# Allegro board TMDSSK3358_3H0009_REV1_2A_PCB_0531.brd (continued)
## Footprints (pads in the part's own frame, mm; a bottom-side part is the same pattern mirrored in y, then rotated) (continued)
CN52271-0679
  rect 0.6x1.9 smd: 1(-2.5,4.225) 2(-1.5,4.225) 3(-0.5,4.225) 4(0.5,4.225) 5(1.5,4.225) 6(2.5,4.225)
  rect 2.1x2.8 smd: 7(-5.65,1.875) 8(5.65,1.875)
CNFPC1X40-0P5MM
  rect 0.25x1.2 smd: 1(-9.75,3.575) 2(-9.25,3.575) 3(-8.75,3.575) 4(-8.25,3.575) 5(-7.75,3.575) 6(-7.25,3.575) 7(-6.75,3.575) 8(-6.25,3.575) 9(-5.75,3.575) 10(-5.25,3.575) 11(-4.75,3.575) 12(-4.25,3.575) 13(-3.75,3.575) 14(-3.25,3.575) 15(-2.75,3.575) 16(-2.25,3.575) 17(-1.75,3.575) 18(-1.25,3.575) 19(-0.75,3.575) 20(-0.25,3.575) 21(0.25,3.575) 22(0.75,3.575) 23(1.25,3.575) 24(1.75,3.575) 25(2.25,3.575) 26(2.75,3.575) 27(3.25,3.575) 28(3.75,3.575) 29(4.25,3.575) 30(4.75,3.575) 31(5.25,3.575) 32(5.75,3.575) 33(6.25,3.575) 34(6.75,3.575) 35(7.25,3.575) 36(7.75,3.575) 37(8.25,3.575) 38(8.75,3.575) 39(9.25,3.575) 40(9.75,3.575)
  custom 0.6x0.6 smd: 41(-11.85,0.875) 42(11.85,0.875)
CNMM8130-CUS-TI
  rect 0.58x0.5 smd: 1(-1.05,0) 4(1.05,0)
  rect 0.8x0.75 smd: 2(-0.95,-1.025) 3(0.95,-1.025) 5(0.95,1.025) 6(-0.95,1.025)
DLW5BTN501SQ2
  custom 0.425x0.425 smd: 1(-1.6,-1.5) 2(1.6,-1.5) 3(1.6,1.5) 4(-1.6,1.5)
DRCPSO_10PIN
  rect 0.8x0.25 smd: 1(-1.5,1) 2(-1.5,0.5) 3(-1.5,0) 4(-1.5,-0.5) 5(-1.5,-1) 6(1.5,-1) 7(1.5,-0.5) 8(1.5,0) 9(1.5,0.5) 10(1.5,1)
  custom 0.412x0.412 smd: 11(0,0)
GMD2_2PIN
  rect 0.31x0.23 smd: 1(0,-0.19) 2(0,0.19)
HEADER10X2
  rect 0.711x2.87 smd: 1(-5.715,-2.705) 2(-5.715,2.705) 3(-4.445,-2.705) 4(-4.445,2.705) 5(-3.175,-2.705) 6(-3.175,2.705) 7(-1.905,-2.705) 8(-1.905,2.705) 9(-0.635,-2.705) 10(-0.635,2.705) 11(0.635,-2.705) 12(0.635,2.705) 13(1.905,-2.705) 14(1.905,2.705) 15(3.175,-2.705) 16(3.175,2.705) 17(4.445,-2.705) 18(4.445,2.705) 19(5.715,-2.705) 20(5.715,2.705)
HEADER_4X1
  rect 1.651x1.651 hole 1.016: 1(0,0)
  round 1.651 hole 1.016: 2(2.54,0) 3(5.08,0) 4(7.62,0)
HEADER_6X1
  rect 1.651x1.651 hole 1.016: 1(0,0)
  round 1.651 hole 1.016: 2(2.54,0) 3(5.08,0) 4(7.62,0) 5(10.16,0) 6(12.7,0)
HF70ACB201209
  rect 1x1 smd: 1(-1,0) 2(1,0)
LGA16PIN_3X3
  rect 0.45x0.35 smd: 1(-1.25,1) 2(-1.25,0.5) 3(-1.25,0) 4(-1.25,-0.5) 5(-1.25,-1) 9(1.25,-1) 10(1.25,-0.5) 11(1.25,0) 12(1.25,0.5) 13(1.25,1)
  rect 0.35x0.45 smd: 6(-0.5,-1.25) 7(0,-1.25) 8(0.5,-1.25) 14(0.5,1.25) 15(0,1.25) 16(-0.5,1.25)
LQFP64PIN
  rect 1.651x0.305 smd: 1(-5.6,3.75) 2(-5.6,3.25) 3(-5.6,2.75) 4(-5.6,2.25) 5(-5.6,1.75) 6(-5.6,1.25) 7(-5.6,0.75) 8(-5.6,0.25) 9(-5.6,-0.25) 10(-5.6,-0.75) 11(-5.6,-1.25) 12(-5.6,-1.75) 13(-5.6,-2.25) 14(-5.6,-2.75) 15(-5.6,-3.25) 16(-5.6,-3.75) 33(5.6,-3.75) 34(5.6,-3.25) 35(5.6,-2.75) 36(5.6,-2.25) 37(5.6,-1.75) 38(5.6,-1.25) 39(5.6,-0.75) 40(5.6,-0.25) 41(5.6,0.25) 42(5.6,0.75) 43(5.6,1.25) 44(5.6,1.75) 45(5.6,2.25) 46(5.6,2.75) 47(5.6,3.25) 48(5.6,3.75)
  rect 0.305x1.651 smd: 17(-3.75,-5.6) 18(-3.25,-5.6) 19(-2.75,-5.6) 20(-2.25,-5.6) 21(-1.75,-5.6) 22(-1.25,-5.6) 23(-0.75,-5.6) 24(-0.25,-5.6) 25(0.25,-5.6) 26(0.75,-5.6) 27(1.25,-5.6) 28(1.75,-5.6) 29(2.25,-5.6) 30(2.75,-5.6) 31(3.25,-5.6) 32(3.75,-5.6) 49(3.75,5.6) 50(3.25,5.6) 51(2.75,5.6) 52(2.25,5.6) 53(1.75,5.6) 54(1.25,5.6) 55(0.75,5.6) 56(0.25,5.6) 57(-0.25,5.6) 58(-0.75,5.6) 59(-1.25,5.6) 60(-1.75,5.6) 61(-2.25,5.6) 62(-2.75,5.6) 63(-3.25,5.6) 64(-3.75,5.6)
MC-306
  rect 1.3x1.9 smd: 1(-2.75,-1.6) 2(2.75,-1.6) 3(2.75,1.6) 4(-2.75,1.6)
MH188X90PL
  round 4.775 hole 2.286: 1(0,0)
MIPF2016
  rect 0.8x1.8 smd: 1(-0.8,0) 2(0.8,0)
MOD17X10-62P
  rect 1.3x0.6 smd: 1(-4.35,6) 2(-4.35,5) 3(-4.35,4) 4(-4.35,3) 5(-4.35,2) 6(-4.35,1) 7(-4.35,0) 8(-4.35,-1) 9(-4.35,-2) 10(-4.35,-3) 11(-4.35,-4) 12(-4.35,-5) 13(-4.35,-6) 23(4.35,-6) 24(4.35,-5) 25(4.35,-4) 26(4.35,-3) 27(4.35,-2) 28(4.35,-1) 29(4.35,0) 30(4.35,1) 31(4.35,2) 32(4.35,3) 33(4.35,4) 34(4.35,5) 35(4.35,6)
  rect 0.6x1.3 smd: 14(-4,-7.85) 15(-3,-7.85) 16(-2,-7.85) 17(-1,-7.85) 18(0,-7.85) 19(1,-7.85) 20(2,-7.85) 21(3,-7.85) 22(4,-7.85) 36(4,7.85) 37(3,7.85) 38(2,7.85) 39(1,7.85) 40(0,7.85) 41(-1,7.85) 42(-2,7.85) 43(-3,7.85) 44(-4,7.85)
  rect 1x0.6 smd: 45(-1.5,4) 46(-1.5,2.4) 47(-1.5,0.8) 48(-1.5,-0.8) 49(-1.5,-2.4) 50(-1.5,-4) 51(0,-4) 52(1.5,-4) 53(1.5,-2.4) 54(1.5,-0.8) 55(1.5,0.8) 56(1.5,2.4) 57(1.5,4) 58(0,4) 59(0,2.4) 60(0,0.8) 61(0,-0.8) 62(0,-2.4)
QFN28_5X5
  rect 0.95x0.305 smd: 1(-2.4,1.5) 2(-2.4,1) 3(-2.4,0.5) 4(-2.4,0) 5(-2.4,-0.5) 6(-2.4,-1) 7(-2.4,-1.5) 15(2.4,-1.5) 16(2.4,-1) 17(2.4,-0.5) 18(2.4,0) 19(2.4,0.5) 20(2.4,1) 21(2.4,1.5)
  rect 0.305x0.95 smd: 8(-1.5,-2.4) 9(-1,-2.4) 10(-0.5,-2.4) 11(0,-2.4) 12(0.5,-2.4) 13(1,-2.4) 14(1.5,-2.4) 22(1.5,2.4) 23(1,2.4) 24(0.5,2.4) 25(0,2.4) 26(-0.5,2.4) 27(-1,2.4) 28(-1.5,2.4)
  rect 3.302x3.302 smd: 29(0,0)
QFN48
  rect 0.8x0.2 smd: 1(-3.075,2.2) 2(-3.075,1.8) 3(-3.075,1.4) 4(-3.075,1) 5(-3.075,0.6) 6(-3.075,0.2) 7(-3.075,-0.2) 8(-3.075,-0.6) 9(-3.075,-1) 10(-3.075,-1.4) 11(-3.075,-1.8) 12(-3.075,-2.2) 25(3.075,-2.2) 26(3.075,-1.8) 27(3.075,-1.4) 28(3.075,-1) 29(3.075,-0.6) 30(3.075,-0.2) 31(3.075,0.2) 32(3.075,0.6) 33(3.075,1) 34(3.075,1.4) 35(3.075,1.8) 36(3.075,2.2)
  rect 0.2x0.8 smd: 13(-2.2,-3.075) 14(-1.8,-3.075) 15(-1.4,-3.075) 16(-1,-3.075) 17(-0.6,-3.075) 18(-0.2,-3.075) 19(0.2,-3.075) 20(0.6,-3.075) 21(1,-3.075) 22(1.4,-3.075) 23(1.8,-3.075) 24(2.2,-3.075) 37(2.2,3.075) 38(1.8,3.075) 39(1.4,3.075) 40(1,3.075) 41(0.6,3.075) 42(0.2,3.075) 43(-0.2,3.075) 44(-0.6,3.075) 45(-1,3.075) 46(-1.4,3.075) 47(-1.8,3.075) 48(-2.2,3.075)
  rect 3.8x3.8 smd: 49(0,0)
RAPC712
  round 4.064 hole 3.556: 1(0,0)
  round 3.683 hole 3.048: 2(-2.997,-4.801) 3(-6.248,0)
SD-MICRO-SCHA5B0300
  rect 0.914x0.457 smd: 1(-7.257,0) 2(-7.257,-0.7) 3(-7.257,-1.4) 4(-7.257,-2.1) 5(7.257,-2.1) 6(7.257,-1.4) 7(7.257,-0.7) 8(7.257,0)
  rect 0.508x0.889 smd: 9(3.775,9.989) 10(-5.975,9.989)
  rect 0.889x2.007 smd: 11(-7.25,7.635) 12(7.25,6.335)
  rect 1.118x1.524 smd: 13(-7.196,-3.365) 14(7.196,-3.365)
  rect 1.194x1.092 smd: 15(-3.425,10.488) 16(2.575,10.488)
SJ3524SMT4PIN
  round 1.702 hole 1.702 unplated: (-8.1,-3.95) (-1.1,-3.95)
  rect 2.21x2.794 smd: 1(0,-0.253) 3(-2,-7.647)
  rect 2.794x2.794 smd: 2(-9.4,-0.253) 10(-13.5,-4.703)
SM-7351-CAP-0402
  round 0.635 smd: 1(-0.508,0) 2(0.508,0)
SM-7351-CAP-0603
  rect 1.092x1.041 smd: 1(-0.85,0) 2(0.85,0)
SM-7351-CAP-0805
  rect 1.346x1.524 smd: 1(-1,0) 2(1,0)
SM-7351-CAP-1206
  rect 1.2x1.85 smd: 1(1.6,0) 2(-1.6,0)
SM-7351-CAP-SMDCAN
  rect 4.15x1.65 smd: 1(3.05,0) 2(-3.05,0)
SM-7351-IND-0805
  rect 1.397x1.549 smd: 1(-0.95,0) 2(0.95,0)
SM-7351-RES-0402
  round 0.635 smd: 1(-0.508,0) 2(0.508,0)
SM-7351-RES-0603
  rect 1.143x1.092 smd: 1(-0.9,0) 2(0.9,0)
SM-7351-RES-0805
  rect 1.143x1.549 smd: 1(-1.1,0) 2(1.1,0)
SM_LED_0805
  rect 1.15x1.194 smd: 1(1.125,0) 2(-1.125,0)
SM_OSC_ABM3
  rect 1.9x2.4 smd: 1(-2.05,0) 2(2.05,0)
SM_RES_0805_KELV
  rect 1.4x1.65 smd: 1(-1.3,0) 2(1.3,0)
  rect 0.127x0.127 smd: 3(-0.377,-1.186) 4(0.377,-1.186)
SM_RPAK_EXB-2HV
  rect 0.406x0.508 smd: 1(-1.83,-0.75) 8(1.83,-0.75) 9(1.83,0.75) 16(-1.83,0.75)
  rect 0.254x0.508 smd: 2(-1.25,-0.75) 3(-0.75,-0.75) 4(-0.25,-0.75) 5(0.25,-0.75) 6(0.75,-0.75) 7(1.25,-0.75) 10(1.25,0.75) 11(0.75,0.75) 12(0.25,0.75) 13(-0.25,0.75) 14(-0.75,0.75) 15(-1.25,0.75)
SMCJ15CA
  rect 2.4x3.3 smd: 1(-3.3,0) 2(3.3,0)
SMD0201
  rect 0.3x0.3 smd: 1(-0.3,0) 2(0.3,0)
SMD1206-ANTENNA
  rect 1.6x1.9 smd: 1(-1.4,0) 2(1.4,0)
SMD_MELF0102
  rect 1x1.2 smd: 1(-1,0) 2(1,0)
SMD_SLF7055T
  rect 1.5x2.2 smd: 1(-3.15,0) 2(3.15,0)
SMDFUSEBLK
  rect 4.242x3.81 smd: 1(-3.175,0) 2(3.175,0)
SMDSC70-5
  rect 0.406x1.016 smd: 1(-0.65,-0.95) 2(0,-0.95) 3(0.65,-0.95) 4(0.65,0.95) 5(-0.65,0.95)
SOIC_8
  rect 0.61x2.184 smd: 1(-1.905,-2.603)
  oval 0.61x2.184 smd: 2(-0.635,-2.603) 3(0.635,-2.603) 4(1.905,-2.603) 5(1.905,2.603) 6(0.635,2.603) 7(-0.635,2.603) 8(-1.905,2.603)
SOJ2_4X3_6-12
  rect 0.95x0.25 smd: 1(-1.375,1.25) 2(-1.375,0.75) 3(-1.375,0.25) 4(-1.375,-0.25) 5(-1.375,-0.75) 6(-1.375,-1.25) 7(1.375,-1.25) 8(1.375,-0.75) 9(1.375,-0.25) 10(1.375,0.25) 11(1.375,0.75) 12(1.375,1.25)
SOT23-3
  rect 0.787x0.889 smd: D(0,1.003) G(-0.94,-1.003) S(0.94,-1.003)
SOT23-6
  rect 0.635x1.016 smd: 1(-0.953,-1.295) 2(0,-1.295) 3(0.953,-1.295) 4(0.953,1.295) 5(0,1.295) 6(-0.953,1.295)
SOT223_6PIN
  rect 0.991x1.499 smd: 1(-2.54,-3.15) 2(-1.27,-3.15) 3(0,-3.15) 4(1.27,-3.15) 5(2.54,-3.15)
  rect 3.277x1.499 smd: 6(0,3.15)
SW_B3SL-1022P
  rect 2.75x1 smd: 1(2.875,-2) 2(-2.875,-2) 3(2.875,2) 4(-2.875,2)
TH_TP_5002
  round 1.778 hole 1.016: 1(0,0)
TP_SMD1MMCIRCLE
  round 1.016 smd: 1(0,0)
U_5_DCK
  rect 0.432x1.27 smd: 1(0.65,0.775) 2(0,0.775) 3(-0.65,0.775) 4(-0.65,-0.884) 5(0.65,-0.884)
U_5_DRL
  rect 0.3x0.45 smd: 1(-0.5,-0.675) 2(0,-0.675) 3(0.5,-0.675) 4(0.5,0.675) 5(-0.5,0.675)
U_6_DCK
  rect 0.4x0.9 smd: 1(-0.65,-1.1) 2(0,-1.1) 3(0.65,-1.1) 4(0.65,1.1) 5(0,1.1) 6(-0.65,1.1)
U_6_DRY
  rect 0.305x0.508 smd: 1(-0.5,-0.439) 2(0,-0.439) 3(0.5,-0.439) 4(0.5,0.439) 5(0,0.439) 6(-0.5,0.439)
U_8_D
  rect 0.6x2 smd: 1(-1.905,-2.4) 2(-0.635,-2.4) 3(0.635,-2.4) 4(1.905,-2.4) 5(1.905,2.4) 6(0.635,2.4) 7(-0.635,2.4) 8(-1.905,2.4)
U_8_DCU
  rect 0.254x1.27 smd: 1(-0.749,-1.473) 2(-0.249,-1.473) 3(0.249,-1.473) 4(0.749,-1.473) 5(0.749,1.473) 6(0.249,1.473) 7(-0.249,1.473) 8(-0.749,1.473)
U_10_DRC
  rect 0.28x0.85 smd: 1(-1,-1.475) 2(-0.5,-1.475) 3(0,-1.475) 4(0.5,-1.475) 5(1,-1.475) 6(1,1.475) 7(0.5,1.475) 8(0,1.475) 9(-0.5,1.475) 10(-1,1.475)
  custom 0.41x0.41 smd: PAD(0,0)
U_10_RSE
  rect 0.3x0.58 smd: 1(-0.75,-0.635) 2(-0.25,-0.635) 3(0.25,-0.635) 4(0.75,-0.635) 6(0.75,0.635) 7(0.25,0.635) 8(-0.25,0.635) 9(-0.75,0.635)
  rect 0.63x0.35 smd: 5(0.86,0) 10(-0.86,0)
U_16_PW
  rect 0.35x1.6 smd: 1(-2.275,-2.8) 2(-1.625,-2.8) 3(-0.975,-2.8) 4(-0.325,-2.8) 5(0.325,-2.8) 6(0.975,-2.8) 7(1.625,-2.8) 8(2.275,-2.8) 9(2.275,2.8) 10(1.625,2.8) 11(0.975,2.8) 12(0.325,2.8) 13(-0.325,2.8) 14(-0.975,2.8) 15(-1.625,2.8) 16(-2.275,2.8)
U_20_DSBGA
  round 0.254 smd: A1(0.6,-0.8) A2(0.2,-0.8) A3(-0.2,-0.8) A4(-0.6,-0.8) B1(0.6,-0.4) B2(0.2,-0.4) B3(-0.2,-0.4) B4(-0.6,-0.4) C1(0.6,0) C2(0.2,0) C3(-0.2,0) C4(-0.6,0) D1(0.6,0.4) D2(0.2,0.4) D3(-0.2,0.4) D4(-0.6,0.4) E1(0.6,0.8) E2(0.2,0.8) E3(-0.2,0.8) E4(-0.6,0.8)
U_48_RSL
  rect 0.85x0.2 smd: 1(-2.975,2.2) 2(-2.975,1.8) 3(-2.975,1.4) 4(-2.975,1) 5(-2.975,0.6) 6(-2.975,0.2) 7(-2.975,-0.2) 8(-2.975,-0.6) 9(-2.975,-1) 10(-2.975,-1.4) 11(-2.975,-1.8) 12(-2.975,-2.2) 25(2.975,-2.2) 26(2.975,-1.8) 27(2.975,-1.4) 28(2.975,-1) 29(2.975,-0.6) 30(2.975,-0.2) 31(2.975,0.2) 32(2.975,0.6) 33(2.975,1) 34(2.975,1.4) 35(2.975,1.8) 36(2.975,2.2)
  rect 0.2x0.85 smd: 13(-2.2,-2.975) 14(-1.8,-2.975) 15(-1.4,-2.975) 16(-1,-2.975) 17(-0.6,-2.975) 18(-0.2,-2.975) 19(0.2,-2.975) 20(0.6,-2.975) 21(1,-2.975) 22(1.4,-2.975) 23(1.8,-2.975) 24(2.2,-2.975) 37(2.2,2.975) 38(1.8,2.975) 39(1.4,2.975) 40(1,2.975) 41(0.6,2.975) 42(0.2,2.975) 43(-0.2,2.975) 44(-0.6,2.975) 45(-1,2.975) 46(-1.4,2.975) 47(-1.8,2.975) 48(-2.2,2.975)
  rect 4.05x4.05 smd: PPAD(-0.225,0.225)
unnamed
  round 1.016 smd: 1(0,0)
USB_STD_A_TH
  round 1.422 hole 0.914: 1(0,0) 2(2.5,0) 3(4.5,0) 4(7,0)
  round 2.794 hole 2.311: S1(-3.073,-2.718) S2(10.058,-2.718)
USP1_2SQR-3
  rect 0.35x0.4 smd: 1(-0.3,0.475) 2(0.3,0.475)
  custom 0.175x0.175 smd: 3(0,-0.325)
VLCF5020T
  custom 0.525x0.525 smd: 1(-1.7,0) 2(1.7,0)
VQFN48_RGZ
  rect 0.85x0.28 smd: 1(-3.475,2.75) 2(-3.475,2.25) 3(-3.475,1.75) 4(-3.475,1.25) 5(-3.475,0.75) 6(-3.475,0.25) 7(-3.475,-0.25) 8(-3.475,-0.75) 9(-3.475,-1.25) 10(-3.475,-1.75) 11(-3.475,-2.25) 12(-3.475,-2.75) 25(3.475,-2.75) 26(3.475,-2.25) 27(3.475,-1.75) 28(3.475,-1.25) 29(3.475,-0.75) 30(3.475,-0.25) 31(3.475,0.25) 32(3.475,0.75) 33(3.475,1.25) 34(3.475,1.75) 35(3.475,2.25) 36(3.475,2.75)
  rect 0.28x0.85 smd: 13(-2.75,-3.475) 14(-2.25,-3.475) 15(-1.75,-3.475) 16(-1.25,-3.475) 17(-0.75,-3.475) 18(-0.25,-3.475) 19(0.25,-3.475) 20(0.75,-3.475) 21(1.25,-3.475) 22(1.75,-3.475) 23(2.25,-3.475) 24(2.75,-3.475) 37(2.75,3.475) 38(2.25,3.475) 39(1.75,3.475) 40(1.25,3.475) 41(0.75,3.475) 42(0.25,3.475) 43(-0.25,3.475) 44(-0.75,3.475) 45(-1.25,3.475) 46(-1.75,3.475) 47(-2.25,3.475) 48(-2.75,3.475)
  rect 5.15x5.15 smd: TPAD(0,0)
XTAL4_3P2X2P5_SMD
  rect 1.397x1.143 smd: 1(-1.1,-0.8) 2(1.1,-0.8) 3(1.1,0.8) 4(-1.1,0.8)
XTAL4_3P2X5SMD
  rect 1.6x1.27 smd: 1(-1.854,-1.105) 2(1.854,-1.105) 3(1.854,1.105) 4(-1.854,1.105)
ZX62-AB-5PA
  rect 1.9x1.9 smd: (-1.2,-2.675) (1.2,-2.675)
  rect 0.4x1.35 smd: 1(-1.3,0) 2(-0.65,0) 3(0,0) 4(0.65,0) 5(1.3,0)
  rect 2.1x1.6 smd: S1(-3.1,-0.125) S2(3.1,-0.125)
  rect 1.8x1.9 smd: S3(-4.1,-2.675) S4(4.1,-2.675)

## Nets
AGND_AUD: C146.2 C150.2 C153.2 C155.2 C156.2 C157.2 C159.2 C160.2 C161.2 C163.2 C164.2 C166.2 C177.2 C178.2 C179.2 C278.2 C280.2 C281.2 FB10.1 J13.1(P1) U31.15(AVSS_ADC) U31.20(DRVSS#20) U31.21(DRVSS#21) U31.26(AVSS_DAC) U31.TPAD
DGND: A1.1(GND#1) A1.4(GND#4) A1.13(GND#13) A1.20(GND#20) A1.22(GND#22) A1.31(GND#31) A1.35(GND#35) A1.36(GND#36) A1.37(GND#37) A1.38(GND#38) A1.39(GND#39) A1.41(GND#41) A1.42(GND#42) A1.43(GND#43) A1.44(GND#44) A1.45(GND#45) A1.46(GND#46) A1.47(GND#47) A1.48(GND#48) A1.49(GND#49) A1.50(GND#50) A1.51(GND#51) A1.52(GND#52) A1.53(GND#53) A1.54(GND#54) A1.55(GND#55) A1.56(GND#56) A1.57(GND#57) A1.58(GND#58) A1.59(GND#59) A1.60(GND#60) A1.61(GND#61) A1.62(GND#62) C1.2 C2.2 C3.2 C4.1 C5.2 C6.1 C7.2 C8.1 C9.1 C10.1 C11.2 C12.2 C13.2 C14.2 C15.2 C16.2 C17.1 C18.2 C19.2 C20.2 C21.2 C22.2 C23.2 C24.2 C25.2 C26.2 C27.2 C28.2 C29.2 C30.2 C31.2 C32.2 C33.2 C34.2 C35.2 C36.2 C37.2 C38.2 C39.2 C40.2 C41.2 C42.2 C43.2 C44.2 C45.2 C46.2 C47.2 C48.2 C49.2 C50.2 C51.2 C52.2 C53.2 C54.2 C55.2 C56.2 C57.2 C58.2 C59.2 C60.2 C61.2 C62.2 C63.2 C64.2 C65.2 C66.2 C67.2 C68.2 C69.2 C70.2 C71.2 C72.2 C73.2 C74.2 C75.2 C76.2 C77.2 C78.2 C79.2 C80.2 C81.2 C82.2 C83.2 C84.2 C85.2 C86.2 C87.2 C90.2 C91.2 C92.2 C93.2 C94.2 C96.2 C97.2 C98.2 C100.2 C101.2 C102.2 C103.2 C104.2 C105.2 C106.2 C107.2 C108.2 C109.2 C110.2 C111.2 C112.2 C113.2 C114.2 C115.2 C116.2 C117.2 C118.2 C119.2 C120.2 C121.2 C122.2 C123.2 C124.2 C125.2 C126.2 C127.2 C128.2 C129.2 C130.2 C131.2 C132.2 C133.2 C134.2 C135.2 C136.2 C137.2 C138.2 C139.2 C140.2 C141.2 C142.2 C143.2 C144.2 C145.2 C147.2 C148.2 C149.2 C151.2 C152.2 C154.2 C158.2 C162.2 C165.2 C168.2 C169.2 C170.2 C171.2 C172.2 C173.2 C174.2 C175.2 C176.2 C180.2 C182.2 C183.2 C184.1 C186.2 C187.2 C188.2 C189.2 C190.2 C191.2 C192.2 C193.2 C194.1 C195.2 C196.1 C197.2 C198.2 C199.2 C200.2 C201.1 C202.1 C203.2 C204.2 C205.2 C206.2 C207.2 C208.1 C209.1 C210.2 C211.2 C212.2 C213.2 C214.2 C215.2 C216.2 C217.2 C218.2 C219.2 C220.2 C221.2 C222.2 C223.2 C224.2 C225.2 C226.2 C227.2 C228.2 C229.2 C230.2 C231.2 C232.2 C233.1 C234.1 C235.2 C236.2 C237.2 C238.2 C239.2 C240.2 C241.1 C242.2 C243.2 C244.2 C246.2 C248.2 C251.1 C252.2 C253.1 C254.2 C255.2 C256.2 C258.2 C259.2 C260.2 C261.2 C262.2(NEG) C263.2 C264.2 C265.2 C266.2 C267.2 C268.2 C269.2 C270.2 C271.2 C272.2 C273.2 C274.2 C275.2 C276.2 C277.2 C279.2 D5.1(CATHODE) D6.2(ANODE) D7.2(ANODE) FB1.1 FB8.2 FB10.2 FB12.1 FB13.1 J1.3 J1.29 J1.36 J1.41 J1.42 J2.2 J3.5(GND) J4.6(VSS) J4.9(GND) J5.4(GND) J6.1 J6.D2 J6.D3 J7.1 J7.D2 J7.D3 J8.1 J10.2(G#2) J10.3(G#3) J10.5(G#5) J10.6(G#6) J11.4 J12.8(GND#8) J12.10(GND#10) J12.12(GND#12) J12.16(GND#16) J12.20(GND#20) L13.2 MH1.1 MH2.1 MH3.1 MH4.1 Q1.S(SOURCE) Q2.S(SOURCE) Q3.S(SOURCE) Q4.S(SOURCE) Q5.S(SOURCE) R12.1(P1) R14.1(P1) R18.1(P1) R31.1(P1) R32.1(P1) R33.1(P1) R34.1(P1) R35.1(P1) R36.1(P1) R37.1(P1) R38.1(P1) R39.1(P1) R40.1(P1) R41.1(P1) R42.1(P1) R43.1(P1) R44.1(P1) R45.1(P1) R46.1(P1) R49.1(P1) R50.1(P1) R53.1(P1) R60.1(P1) R61.1(P1) R62.1(P1) R63.1(P1) R64.1(P1) R66.1(P1) R68.1(P1) R70.1(P1) R85.2(P2) R94.1 R95.2 R98.1(P1) R99.2 R100.1(P1) R101.1(P1) R104.1(P1) R105.1(P1) R109.2(P2) R119.1 R125.1(P1) R127.2(P2) R143.1(P1) R145.1(P1) R146.1(P1) R165.1(P1) R166.1(P1) R172.1(P1) R193.1(P1) R198.1(P1) R199.1(P1) R202.1(P1) R205.1(P1) R207.1(P1) R209.1(P1) R210.2(P2) R214.1 R215.1(P1) R218.1 R222.1(P1) R226.1(P1) R231.1(P1) R235.2 R236.1(P1) R242.1 R245.2 SW5.1 SW5.2 SW7.1 SW7.2 TP2.1 TP13.1 U1.5(GND) U2.4(GND) U3.3(GND#3) U3.6(GND#6) U4.3(GND) U5.2(GND) U6.3(GND) U7.4(GND) U7.7(FSW) U7.8(PGND) U7.PAD(TPAD) U8.1(A0) U8.2(A1) U8.3(A2) U8.4(VSS) U9.2(GND) U10.5(GND#5) U10.10(RSV0) U10.12(GND#12) U10.13(GND#13) U10.16(GND#16) U11.3(2DIR) U11.8(GND#8) U11.9(GND#9) U11.14(2O\E\) U11.15(1O\E\) U12.2(1DIR) U12.8(GND#8) U12.9(GND#9) U12.14(2O\E\) U12.15(1O\E\) U13.3(GND#3) U13.6(GND#6) U14.4(PGND) U14.8(GND) U14.11(PWRPD) U15.4(GND) U16.6(TEST) U16.29(VSS(FLAG)) U17.4(GND) U18.1(GND) U19.4(GND) U20.B4(SYNC) U20.C1(PGND#C1) U20.C2(PGND#C2) U20.C3(GND#C3) U20.D3(GND#D3) U20.E4(GND#E4) U21.2(GND) U22.3(VSS) U23.49(EP) U24.49(EP) U25.15(GNDIO) U25.17(REFGND) U25.20(OSC32KIN) U25.26(BOOT0) U25.34(GND1) U25.43(GND2) U25.PPAD(GNDP) U26.A1(VSS#A1) U26.A18(VSS#A18) U26.F8(VSS#F8) U26.G8(VSS#G8) U26.G9(VSS#G9) U26.G11(VSS#G11) U26.G12(VSS#G12) U26.H6(VSS#H6) U26.H7(VSS#H7) U26.H8(VSS#H8) U26.H9(VSS#H9) U26.H10(VSS#H10) U26.H12(VSS#H12) U26.J6(VSS#J6) U26.J7(VSS#J7) U26.J8(VSS#J8) U26.J9(VSS#J9) U26.J10(VSS#J10) U26.J11(VSS#J11) U26.K7(VSS#K7) U26.K9(VSS#K9) U26.K10(VSS#K10) U26.K11(VSS#K11) U26.L10(VSS#L10) U26.L11(VSS#L11) U26.L12(VSS#L12) U26.L13(VSS#L13) U26.M6(VSS#M6) U26.M7(VSS#M7) U26.M8(VSS#M8) U26.M9(VSS#M9) U26.M10(VSS#M10) U26.M12(VSS#M12) U26.M14(VSSA_USB#M14) U26.N7(VSS#N7) U26.N10(VSS#N10) U26.N11(VSS#N11) U26.N14(VSSA_USB#N14) U26.V1(VSS#V1) U26.V18(VSS#V18) U27.3(GND#3) U27.6(GND#6) U28.1(GND.1) U28.5(GND.2) U28.10(AGND) U28.11(GND.3) U28.13(TEST) U28.15(GND.4) U28.25(GND.5) U28.32(ACBUS5) U28.35(GND.6) U28.47(GND.7) U28.51(GND.8) U29.6(2A1) U29.8(GND#8) U29.9(GND#9) U29.14(2O\E\) U29.15(1O\E\) U30.3 U31.42(DVSS) U31.43(SELECT) U32.A9(VSS1) U32.B1(VSSQ1) U32.B3(VSS2) U32.B9(VSSQ2) U32.D1(VSSQ3) U32.D8(VSSQ4) U32.E1(VSS3) U32.E2(VSSQ5) U32.E8(VSSQ6) U32.F9(VSSQ7) U32.G1(VSSQ8) U32.G8(VSS4) U32.G9(VSSQ9) U32.J2(VSS5) U32.J8(VSS6) U32.M1(VSS7) U32.M9(VSS8) U32.P1(VSS9) U32.P9(VSS10) U32.T1(VSS11) U32.T9(VSS12) Y2.6(GND)
GND_IN: J9.2 J9.3 U30.4
GND_OSC0: C95.2 C245.1 C250.1 U26.V11(VSS_OSC)
GND_OSC1: C247.1 C249.1 U26.A5(VSS_RTC)
GNDA_ADC: C99.2 FB8.1 R72.1(P1) U26.E8(VSSA_ADC)
GNDA_TSC: C88.2 C89.2 R72.2(P2) U26.A8(AIN6) U26.A9(VREFN) U26.B8(AIN5) U26.C8(AIN4) U26.C9(AIN7)
V1_8D: C149.1 C152.1 C170.1 C264.1 C270.1 C276.1 L7.1 R57.2(P2) R58.2(P2) R182.2(P2) R183.2(P2) R184.2(P2) R185.2(P2) U11.16(VCCB) U12.16(VCCB) U13.4(OUT) U29.16(VCCB) U31.36(DVDD)
V3_3AUD: C177.1 C178.1 C179.1 C278.1 C280.1 C281.1 FB11.2 U31.16(DRVDD#16) U31.17(DRVDD#17) U31.24(DRVDD#24) U31.25(AVDD_DAC)
V3_3D: C5.1 C11.1 C12.1 C13.1 C14.1 C15.1 C16.1 C20.1 C26.1 C34.1 C35.1 C38.1 C39.1 C133.1 C139.1 C151.1 C180.1 C184.2 C194.2 C196.2 C231.1 C246.1 C259.1 C265.1 C266.1 C272.1 C274.1 C275.1 FB11.1 FB15.1 FB16.1 FB18.1 FB19.1 FB20.1 J1.4 J2.1 J8.4 J11.1 J12.5(TVDD) R13.2 R16.1 R76.1 R82.1 R83.1 R86.2(P2) R90.1 R106.2(P2) R110.2 R118.2 R221.2(P2) R225.2(P2) R234.2 U3.4(OUT) U4.5(VCC) U5.5(VCC) U9.6(VCC) U10.1(VDD_IO) U10.14(VDD) U10.15(RSV1) U11.1(VCCA) U11.2(1DIR) U12.1(VCCA) U12.3(2DIR) U16.4(VDD33#4) U16.10(VDDCRREF/VDD33) U16.14(VDD33#14) U16.20(VDD33#20) U16.27(VDDPLLREF/VDD33) U23.4(VDD33) U24.4(VDD33) U28.20(VCCIO.1) U28.28(ACBUS2) U28.31(VCCIO.2) U28.42(VCCIO.3) U28.56(VCCIO.4) U29.1(VCCA) U29.2(1DIR) U29.3(2DIR) U31.44(IOVDD) U31.45(MFP0) U31.46(MFP1)
V5_0D: C21.1 C22.1 C207.1 R15.2(P2) R19.2(P2) U18.2(IN#2) U18.3(IN#3) U20.E1(VOUT#E1) U20.E2(VOUT#E2)
V5_0D_EN: R120.1(P1) U20.A4(EN)
VBAT: C23.1 C24.1 C25.1 C33.1 C42.1 C43.1 C46.1 C63.1 C74.1 C76.1 C77.1 C97.1 C124.1 C132.1 C137.1 C138.1 C154.1 C217.1 C252.1 C262.1(POS) D7.1(CATHODE) F1.2 R111.2(P2) R112.2(P2) R113.2(P2) R114.2(P2) R116.2(P2) TP5.1 TP11.1 U3.2(IN) U7.2(VIN) U13.2(IN) U20.A1(VIN#A1) U20.A2(VIN#A2) U21.1(IN) U21.3(EN) U25.3(VCC3) U25.6(VCC6) U25.13(VCCIO) U25.23(VCC5) U25.27(VBACKUP) U25.28(VCC7) U25.36(VCC1) U25.41(VCC2) U25.47(VCC4) U27.2(IN)
VBAT_WLAN: C69.1 C70.1 L6.2 Y2.1(VIO) Y2.12(VDD)
VBAT_WLAN_OUT: L6.1 U22.2(VOUT)
VBUS_DET: R101.2(P2) R103.1(P1) U16.18(VBUS_DET)
VDD_1V8FT: C134.1 C241.2 C251.2 C253.2 U28.12(VCORE.1) U28.37(VCORE.2) U28.49(VREGOUT) U28.64(VCORE.3)
VDD_CORE: C49.1 C51.1 C67.1 C91.1 C92.1 C94.1 C100.1 C101.1 C102.1 C103.1 L10.2 U25.44(VFB2) U26.F6(VDD_CORE#F6) U26.F7(VDD_CORE#F7) U26.G6(VDD_CORE#G6) U26.G7(VDD_CORE#G7) U26.G10(VDD_CORE#G10) U26.H11(VDD_CORE#H11) U26.J12(VDD_CORE#J12) U26.K6(VDD_CORE#K6) U26.K8(VDD_CORE#K8) U26.K12(VDD_CORE#K12) U26.L6(VDD_CORE#L6) U26.L7(VDD_CORE#L7) U26.L8(VDD_CORE#L8) U26.L9(VDD_CORE#L9) U26.M11(VDD_CORE#M11) U26.M13(VDD_CORE#M13) U26.N8(VDD_CORE#N8) U26.N9(VDD_CORE#N9) U26.N12(VDD_CORE#N12) U26.N13(VDD_CORE#N13)
VDD_FTREGIN: FB18.2 U28.50(VREGIN)
VDD_FTVPHY: C242.1 FB19.2 U28.4(VPHY)
VDD_FTVPLL: C248.1 FB20.2 U28.9(VPLL)
VDD_MPU: C244.1 L11.2 R201.1(P1) R212.1(I1)
VDD_MPU_AM335X: C82.1 C85.1 C86.1 C104.1 C107.1 C123.1 R212.2(I2) U26.F10(VDD_MPU#F10) U26.F11(VDD_MPU#F11) U26.F12(VDD_MPU#F12) U26.F13(VDD_MPU#F13) U26.G13(VDD_MPU#G13) U26.H13(VDD_MPU#H13) U26.J13(VDD_MPU#J13)
VDD_RTC: C122.1 U26.D6(CAP_VDD_RTC)
VDDA_ADC: C99.1 FB7.1 R73.1(P1) U26.D8(VDDA_ADC)
VDDH_PHY: C41.1 R26.1(P1) R55.1(P1) U23.10(VDDH_REG)
VDDH_PHY2: C37.1 R47.2(P2) R54.1(P1) U24.10(VDDH_REG)
VDDL_PHY: C205.1 C216.1 C224.1 FB17.2 L5.1 R170.1(P1) U23.47(DVDDL)
VDDL_PHY2: C199.1 C200.1 C223.1 FB14.2 L3.1 R169.1(P1) U24.47(DVDDL)
VDDMPU_MON: R223.1(P1) U26.A2(VDD_MPU_MON)
VDDS_DDR: C140.1 C142.1 C143.1 C144.1 C147.1 C148.1 C158.1 C165.1 C167.2 C168.1 C169.1 C172.1 C173.1 C174.1 C175.1 C235.1 C273.1 C277.1 L8.2 R93.2 R237.1 R238.1(I1) U14.2(VLDOIN) U25.16(VFBIO) U32.A1(VDDQ1) U32.A8(VDDQ2) U32.B2(VDD1) U32.C1(VDDQ3) U32.C9(VDDQ4) U32.D2(VDDQ5) U32.D9(VDD9) U32.E9(VDDQ7) U32.F1(VDDQ8) U32.G7(VDD2) U32.H2(VDDQ9) U32.H9(VDDQ10) U32.K2(VDD4) U32.K8(VDD5) U32.N1(VDD6) U32.N9(VDD7) U32.R1(VDD8) U32.R9(VDD3)
VDDS_DDR3_AM335X: C108.1 C109.1 C110.1 C111.1 C112.1 C113.1 C114.1 C118.1 C119.1 C120.1 C121.1 C128.1 C129.1 C130.1 C131.1 C260.1 C261.1 C267.1 C268.1 C269.1 C271.1 R238.2(I2) U26.E5(VDDS_DDR#E5) U26.F5(VDDS_DDR#F5) U26.G5(VDDS_DDR#G5) U26.H5(VDDS_DDR#H5) U26.J5(VDDS_DDR#J5) U26.K5(VDDS_DDR#K5) U26.L5(VDDS_DDR#L5)
VDDSHV1: C105.1 C106.1 C117.1 FB9.1 R115.1(P1) R123.1(P1) U26.P7(VDDSHV1#P7) U26.P8(VDDSHV1#P8)
VDDSHV2: C90.1 C96.1 C203.1 FB5.1 U26.P10(VDDSHV2#P10) U26.P11(VDDSHV2#P11)
VDDSHV3: C28.1 C50.1 C60.1 FB3.1 R22.2(P2) SW3.1 SW3.2 U26.P12(VDDSHV3#P12) U26.P13(VDDSHV3#P13)
VDDSHV4: C1.1 C3.1 C30.1 C57.1 C80.1 FB4.1 J4.4(VDD) R1.2(P2) R2.2(P2) R3.2(P2) R4.2(P2) R5.2(P2) U1.10(VCC) U26.H14(VDDSHV4#H14) U26.J14(VDDSHV4#J14)
VDDSHV5: C29.1 C45.1 C79.1 FB2.1 U26.K14(VDDSHV5#K14) U26.L14(VDDSHV5#L14)
VDDSHV6: C27.1 C93.1 C115.1 C116.1 C126.1 C127.1 C206.1 C255.1 C258.1 FB6.1 R11.2(P2) R74.2(P2) R102.2(P2) R117.2(P2) R131.2(P2) R141.2(P2) R142.2(P2) R149.2(P2) R150.2(P2) R151.2(P2) R152.2(P2) R153.2(P2) R154.2(P2) R155.2(P2) R156.2(P2) R157.2(P2) R158.2(P2) R159.2(P2) R160.2(P2) R161.2(P2) R162.2(P2) R163.2(P2) R164.2(P2) R177.2(P2) R179.2(P2) R191.2(P2) R219.1(P1) U2.1(VCC) U6.5(VCC) U8.8(VCC) U26.E10(VDDSHV6#E10) U26.E11(VDDSHV6#E11) U26.E12(VDDSHV6#E12) U26.E13(VDDSHV6#E13) U26.F14(VDDSHV6#F14) U26.G14(VDDSHV6#G14) U26.N5(VDDSHV6#N5) U26.P5(VDDSHV6#P5) U26.P6(VDDSHV6#P6)
ACC_INT1: U10.11(INT1) U26.C13(MCASP0_FSR)
ACC_INT2: R243.1(P1) R244.2(P2) U26.C18(ECAP0_IN_PWM0_OUT)
AM335X_AUDA_BCLK: U26.H17(MII1_CRS) U31.38(BCLK)
AM335X_AUDA_DIN: U26.H16(MII1_COL) U31.40(DIN)
AM335X_AUDA_DOUT: U26.H18(MII1_REFCLK) U31.41(DOUT)
AM335X_AUDA_FSX: U26.J15(MII1_RXERR) U31.39(WCLK)
AM335X_COM_WL_IRQ: U12.4(1A1) U26.U17(GPMC_WPN)
AM335X_EXT_WAKEUP: R173.2(P2) R189.2(P2) R211.2(P2)
AM335X_EXTINT: C32.1 R21.2(P2) R29.1(P1) R124.2(P2) R167.1(P1) U26.B18(NMIN)
AM335X_GPIO_LED1: Q3.G(GATE) R100.2(P2) U26.T9(GPMC_AD7)
AM335X_GPIO_LED2: Q2.G(GATE) R98.2(P2) U26.R9(GPMC_AD6)
AM335X_GPIO_LED3: Q5.G(GATE) R105.2(P2) U26.V8(GPMC_AD5)
AM335X_GPIO_LED4: Q4.G(GATE) R104.2(P2) U26.U8(GPMC_AD4)
AM335X_I2C0_SCL: J2.3 J8.3 R137.2(P2) R139.2(P2) R142.1(P1) R232.2(P2) U8.6(SCL) U10.4(SCL/SPC) U26.C16(I2C0_SCL)
AM335X_I2C0_SDA: J2.4 J8.2 R138.2(P2) R140.2(P2) R141.1(P1) R233.2(P2) U8.5(SDA) U10.6(SDA/SDI/SDO) U26.C17(I2C0_SDA)
AM335X_LCD_AC_BIAS_EN: RP4.4 U26.R6(LCD_AC_BIAS_EN)
AM335X_LCD_DATA0: R31.2(P2) R164.1(P1) RP1.5 U26.R1(LCD_DATA0)
AM335X_LCD_DATA1: R32.2(P2) R163.1(P1) RP1.4 U26.R2(LCD_DATA1)
AM335X_LCD_DATA2: R33.2(P2) R162.1(P1) RP1.3 U26.R3(LCD_DATA2)
AM335X_LCD_DATA3: R34.2(P2) R161.1(P1) RP1.2 U26.R4(LCD_DATA3)
AM335X_LCD_DATA4: R35.2(P2) R160.1(P1) RP1.1 U26.T1(LCD_DATA4)
AM335X_LCD_DATA5: R36.2(P2) R159.1(P1) RP2.6 U26.T2(LCD_DATA5)
AM335X_LCD_DATA6: R37.2(P2) R158.1(P1) RP2.5 U26.T3(LCD_DATA6)
AM335X_LCD_DATA7: R38.2(P2) R157.1(P1) RP2.4 U26.T4(LCD_DATA7)
AM335X_LCD_DATA8: R39.2(P2) R156.1(P1) RP2.3 U26.U1(LCD_DATA8)
AM335X_LCD_DATA9: R40.2(P2) R155.1(P1) RP2.2 U26.U2(LCD_DATA9)
AM335X_LCD_DATA10: R41.2(P2) R154.1(P1) RP2.1 U26.U3(LCD_DATA10)
AM335X_LCD_DATA11: R42.2(P2) R153.1(P1) RP3.5 U26.U4(LCD_DATA11)
AM335X_LCD_DATA12: R43.2(P2) R152.1(P1) RP3.4 U26.V2(CD_DATA12)
AM335X_LCD_DATA13: R44.2(P2) R151.1(P1) RP3.3 U26.V3(LCD_DATA13)
AM335X_LCD_DATA14: R45.2(P2) R150.1(P1) RP3.2 U26.V4(LCD_DATA14)
AM335X_LCD_DATA15: R46.2(P2) R149.1(P1) RP3.1 U26.T5(LCD_DATA15)
AM335X_LCD_DATA16: RP1.6 U26.U13(GPMC_AD15)
AM335X_LCD_DATA17: RP3.6 U26.V13(GPMC_AD14)
AM335X_LCD_DATA18: RP1.7 U26.R12(GPMC_AD13)
AM335X_LCD_DATA19: RP2.7 U26.T12(GPMC_AD12)
AM335X_LCD_DATA20: RP3.7 U26.U12(GPMC_AD11)
AM335X_LCD_DATA21: RP1.8 U26.T11(GPMC_AD10)
AM335X_LCD_DATA22: RP2.8 U26.T10(GPMC_AD9)
AM335X_LCD_DATA23: RP3.8 U26.U10(GPMC_AD8)
AM335X_LCD_DISEN: RP4.7 U26.U18(GPMC_BEN1)
AM335X_LCD_HSYNC: RP4.6 U26.R5(LCD_HSYNC)
AM335X_LCD_PCLK: RP4.8 U26.V5(LCD_PCLK)
AM335X_LCD_VSYNC: RP4.5 U26.U5(LCD_VSYNC)
AM335X_MCASP0_ACLKX: U26.A13(MCASP0_ACLKX) U29.4(1A1)
AM335X_MCASP0_AHCLKR: A1.6(WLAN_EN) U26.V6(GPMC_CSN0)
AM335X_MCASP0_AHCLKX: U12.7(2A2) U26.A14(MCASP0_AHCLKX)
AM335X_MCASP0_AXR0: U26.D12(MCASP0_AXR0) U29.5(1A2)
AM335X_MCASP0_AXR1: U12.5(1A2) U26.D13(MCASP0_AXR1)
AM335X_MCASP0_FSX: U12.6(2A1) U26.B13(MCASP0_FSX)
AM335X_MMC0_CLK: J4.5(CLOCK) R132.1(P1) U1.1(IO1)
AM335X_MMC0_CMD: J4.3(CMD) R1.1(P1) U1.2(IO2) U26.G18(MMC0_CMD)
AM335X_MMC0_D0: J4.7(DAT0) R2.1(P1) U1.8(IO6) U26.G16(MMC0_DAT0)
AM335X_MMC0_D1: J4.8(DAT1) R5.1(P1) U1.7(IO5) U26.G15(MMC0_DAT1)
AM335X_MMC0_D2: J4.1(DAT2) R4.1(P1) U1.6(IO4) U26.F18(MMC0_DAT2)
AM335X_MMC0_D3: J4.2(CD/DAT3) R3.1(P1) U1.3(IO3) U26.F17(MMC0_DAT3)
AM335X_OSC0_IN: C250.2 R216.2(P2) U26.V10(XTALIN) Y6.3
AM335X_OSC0_OUT: R213.1(P1) U26.U11(XTALOUT)
AM335X_OSC1_IN: C247.2 U26.A6(RTC_XTALIN) Y7.4
AM335X_OSC1_OUT: R217.1(P1) U26.A4(RTC_XTALOUT)
AM335X_RGMII1_MDIO_CLK: R25.2(P2) R147.2(P2) U23.1(MDC) U26.M18(MDIO_CLK)
AM335X_RGMII1_MDIO_DATA: R30.1(P1) R148.2(P2) U23.48(MDIO) U26.M17(MDIO_DATA)
AM335X_RGMII1_RXCLK: R208.2(P2) U26.L18(MII1_RXCLK)
AM335X_RGMII1_RXD0: R204.2(P2) U26.M16(MII1_RXD0)
AM335X_RGMII1_RXD1: R203.2(P2) U26.L15(MII1_RXD1)
AM335X_RGMII1_RXD2: R69.2(P2) U26.L16(MII1_RXD2)
AM335X_RGMII1_RXD3: R71.2(P2) U26.L17(MII1_RXD3)
AM335X_RGMII1_RXDV: R206.2(P2) U26.J17(MII1_RXDV)
AM335X_RGMII1_TXCLK: R134.1(P1) U23.35(GTX_CLK)
AM335X_RGMII1_TXD0: R135.1(P1) U23.36(TXD0)
AM335X_RGMII1_TXD1: R130.1(P1) U23.37(TXD1)
AM335X_RGMII1_TXD2: R136.1(P1) U23.38(TXD2)
AM335X_RGMII1_TXD3: R133.1(P1) U23.39(TXD3)
AM335X_RGMII1_TXEN: R129.1(P1) U23.34(TX_EN)
AM335X_RGMII2_RXCLK: R200.2(P2) U26.T15(GPMC_A7)
AM335X_RGMII2_RXD0: R195.2(P2) U26.V17(GPMC_A11)
AM335X_RGMII2_RXD1: R194.2(P2) U26.T16(GPMC_A10)
AM335X_RGMII2_RXD2: R65.2(P2) U26.U16(GPMC_A9)
AM335X_RGMII2_RXD3: R67.2(P2) U26.V16(GPMC_A8)
AM335X_RGMII2_RXDV: R197.2(P2) U26.V14(GPMC_A1)
AM335X_RGMII2_TXCLK: R168.1(P1) U24.35(GTX_CLK)
AM335X_RGMII2_TXD0: R174.1(P1) U24.36(TXD0)
AM335X_RGMII2_TXD1: R51.1(P1) U24.37(TXD1)
AM335X_RGMII2_TXD2: R180.1(P1) U24.38(TXD2)
AM335X_RGMII2_TXD3: R192.1(P1) U24.39(TXD3)
AM335X_RGMII2_TXEN: R56.1(P1) U24.34(TX_EN)
AM335X_SPI0_CS0: J11.2 R179.1(P1) U26.A16(SPI0_CS0)
AM335X_SPI0_CS1: J4.10(CD) R11.1(P1) U2.3(IO1) U26.C15(SPI0_CS1)
AM335X_SPI0_D0: J11.6 U26.B17(SPI0_D0)
AM335X_SPI0_D1: J11.3 R177.1(P1) U26.B16(SPI0_D1)
AM335X_SPI0_SCLK: J11.5 R171.2(P2)
AM335X_UART0_CTSN: U26.E18(UART0_CTSN) U28.40(BDBUS2)
AM335X_UART0_RTSN: R131.1(P1) U26.E17(UART0_RTSN) U28.41(BDBUS3)
AM335X_UART0_RXD: U26.E15(UART0_RXD) U28.38(BDBUS0)
AM335X_UART0_TXD: U26.E16(UART0_TXD) U28.39(BDBUS1)
AM335X_UART1_CTSN: U11.7(2A2) U26.D18(UART1_CTSN)
AM335X_UART1_RTSN: U11.5(1A2) U26.D17(UART1_RTSN)
AM335X_UART1_RXD: U11.6(2A1) U26.D16(UART1_RXD)
AM335X_UART1_TXD: U11.4(1A1) U26.D15(UART1_TXD)
AM335X_USB0_CE: TP3.1 U26.M15(USB0_CE)
AM335X_USB1_CE: TP6.1 U26.P18(USB1_CE)
AM335X_USB1_DRVVBUS: R127.1(P1) U18.4(EN) U26.F15(USB1_DRVVBUS)
AM335X_USB1_OC: R102.1(P1) U18.5(O\C\) U26.B12(MCASP0_ACLKR)
AM335X_USB1_VBUS: C214.1 D6.1(CATHODE) R126.2 U26.T18(USB1_VBUS)
AM335X_XDMA_EVENT_INTR0: R186.1(P1) U31.37(MCLK)
AM335X_XDMA_EVENT_INTR1: R52.1(P1) U29.7(2A2)
AM335X_XLEFT: J1.39 U26.B6(AIN0)
AM335X_XRIGHT: J1.37 U26.C7(AIN1)
AM335X_YDOWN: J1.38 U26.A7(AIN3)
AM335X_YUP: J1.40 U26.B7(AIN2)
AUD_RESETN: R87.1(P1) U31.33(RESETN)
BKLT_L: L9.1 U7.1(L)
BKLT_SW: L9.2 U7.10(SW)
CAP_TOUCH_INT: R80.2(P2) U26.T13(GPMC_CSN3)
CAP_VBB_MPU: C256.1 U26.C10(CAP_VBB_MPU)
CAP_VDD_SRAM_CORE: C83.1 U26.D9(CAP_VDD_SRAM_CORE)
CAP_VDD_SRAM_MPU: C254.1 U26.D11(CAP_VDD_SRAM_MPU)
CBB0: J1.21 RP3.9
CBB1: J1.22 RP3.10
CBB2: J1.23 RP3.11
CBB3: J1.24 RP3.12
CBB4: J1.25 RP3.13
CBB5: J1.26 RP3.14
CBB6: J1.27 RP3.15
CBB7: J1.28 RP3.16
CBG0: J1.13 RP2.9
CBG1: J1.14 RP2.10
CBG2: J1.15 RP2.11
CBG3: J1.16 RP2.12
CBG4: J1.17 RP2.13
CBG5: J1.18 RP2.14
CBG6: J1.19 RP2.15
CBG7: J1.20 RP2.16
CBR0: J1.5 RP1.9
CBR1: J1.6 RP1.10
CBR2: J1.7 RP1.11
CBR3: J1.8 RP1.12
CBR4: J1.9 RP1.13
CBR5: J1.10 RP1.14
CBR6: J1.11 RP1.15
CBR7: J1.12 RP1.16
CCLK: J1.30 RP4.9
CDEN: J1.34 RP4.13
CHASSIS_ETH1: C9.2 C10.2 J6.SHLD1 J6.SHLD2
CHASSIS_ETH2: C8.2 C17.2 J7.SHLD1 J7.SHLD2
CHASSIS_SD: FB12.2 J4.11(GND3) J4.12(GND4) J4.13(GND5) J4.14(GND6) J4.15(GND7) J4.16(GND8)
CHASSIS_USB0: FB13.2 J3.S1 J3.S2 J3.S3 J3.S4
CHASSIS_USB1: FB1.2 J5.S1 J5.S2
CHSYNC: J1.32 RP4.11
CLK_25M: R190.1(P1) U23.25(CLK_25M)
CLK_25M_R: R24.2(P2) R190.2(P2)
COM_BTRST: A1.10(BT_EN) U12.10(2B2)
COM_BTUARTDEBUG: A1.32(BT_TX_DBG) TP12.1
COM_SLOW_CLK: R188.2(P2) U29.10(2B2)
COM_SLOW_CLK_XO: R187.2(P2) Y2.7(OUT)
COM_WL_RS232_RX: A1.7(RS232_RX) TP15.1
COM_WL_RS232_TX: A1.8(RS232_TX) TP19.1
COM_WL_UART_DBG: A1.5(UART_DBG) TP17.1
COMAUD_CLK: A1.26(AUD_CLK) U29.13(1B1)
COMAUD_FSYNC: A1.25(AUD_FSYNC) U12.11(2B1)
COMAUD_IN: A1.23(AUD_IN) U29.12(1B2)
COMAUD_OUT: A1.24(AUD_OUT) U12.12(1B2)
COMBTUARTCTS: A1.28(UART_CTS) U11.12(1B2)
COMBTUARTRTS: A1.27(UART_RTS) U11.10(2B2)
COMBTUARTRX: A1.30(UART_RX) U11.13(1B1)
COMBTUARTTX: A1.29(UART_TX) U11.11(2B1)
COMWL_IRQ: A1.9(WLAN_IRQ) U12.13(1B1)
CRFILT: C195.1 U16.9(CRFILT)
CVSYNC: J1.33 RP4.12
DDR_A0: RP5.7 U26.F3(DDR_A0) U32.N3(A0)
DDR_A1: RP6.5 U26.H1(DDR_A1) U32.P7(A1)
DDR_A2: RP7.5 U26.E4(DDR_A2) U32.P3(A2)
DDR_A3: RP5.4 U26.C3(DDR_A3) U32.N2(A3)
DDR_A4: RP6.7 U26.C2(DDR_A4) U32.P8(A4)
DDR_A5: RP5.3 U26.B1(DDR_A5) U32.P2(A5)
DDR_A6: RP6.8 U26.D5(DDR_A6) U32.R8(A6)
DDR_A7: RP7.8 U26.E2(DDR_A7) U32.R2(A7)
DDR_A8: RP7.2 U26.D4(DDR_A8) U32.T8(A8)
DDR_A9: RP7.6 U26.C1(DDR_A9) U32.R3(A9)
DDR_A10: RP6.3 U26.F4(DDR_A10) U32.L7(A10)
DDR_A11: RP7.4 U26.F2(DDR_A11) U32.R7(A11)
DDR_A12: RP6.4 U26.E3(DDR_A12) U32.N7(A12)
DDR_A13: RP7.7 U26.H3(DDR_A13) U32.T3(A13)
DDR_A14: RP7.3 U26.H4(DDR_A14) U32.T7(A14)
DDR_BA0: RP5.5 U26.C4(DDR_BA0) U32.M2(BA0)
DDR_BA1: RP6.6 U26.E1(DDR_BA1) U32.N8(BA1)
DDR_BA2: RP5.8 U26.B3(DDR_BA2) U32.M3(BA2)
DDR_CASN: RP6.1 U26.F1(DDR_CASN) U32.K3(CASN)
DDR_CKE: R242.2 RP7.1 U26.G3(DDR_CKE) U32.K9(CKE)
DDR_CLK: R89.1 U26.D2(DDR_CK) U32.J7(CK)
DDR_CLKN: R88.1 U26.D1(DDR_CKN) U32.K7(CKN)
DDR_CSN: RP5.2 U26.H2(DDR_CSN0) U32.L2(CSN)
DDR_D0: U26.M3(DDR_D0) U32.H8(DQ5)
DDR_D1: U26.M4(DDR_D1) U32.H7(DQ7)
DDR_D2: U26.N1(DDR_D2) U32.H3(DQ4)
DDR_D3: U26.N2(DDR_D3) U32.E3(DQ0)
DDR_D4: U26.N3(DDR_D4) U32.G2(DQ6)
DDR_D5: U26.N4(DDR_D5) U32.F2(DQ2)
DDR_D6: U26.P3(DDR_D6) U32.F7(DQ1)
DDR_D7: U26.P4(DDR_D7) U32.F8(DQ3)
DDR_D8: U26.J1(DDR_D8) U32.C3(DQ9)
DDR_D9: U26.K1(DDR_D9) U32.A3(DQ15)
DDR_D10: U26.K2(DDR_D10) U32.A2(DQ13)
DDR_D11: U26.K3(DDR_D11) U32.D7(DQ8)
DDR_D12: U26.K4(DDR_D12) U32.C2(DQ11)
DDR_D13: U26.L3(DDR_D13) U32.B8(DQ14)
DDR_D14: U26.L4(DDR_D14) U32.C8(DQ10)
DDR_D15: U26.M1(DDR_D15) U32.A7(DQ12)
DDR_DQM0: U26.M2(DDR_DQM0) U32.E7(LDM)
DDR_DQM1: U26.J2(DDR_DQM1) U32.D3(UDM)
DDR_DQS0: U26.P1(DDR_DQS0) U32.F3(LDQS)
DDR_DQS1: U26.L1(DDR_DQS1) U32.C7(UDQS)
DDR_DQSN0: U26.P2(DDR_DQSN0) U32.G3(LDQSN)
DDR_DQSN1: U26.L2(DDR_DQSN1) U32.B7(UDQSN)
DDR_ODT: RP5.1 U26.G1(DDR_ODT) U32.K1(ODT)
DDR_RASN: RP6.2 U26.G4(DDR_RASN) U32.J3(RASN)
DDR_RESETN: R237.2 R241.1 U26.G2(DDR_RESETN) U32.T2(RESET#)
DDR_VREF: C125.1 C145.1 C187.1 TP25.1 U14.6(REFOUT) U26.J4(DDR_VREF) U32.H1(VREF_DQ) U32.M8(VREF_CA)
DDR_VTT_EN: R243.2(P2) R245.1 U14.7(EN)
DDR_WEN: RP5.6 U26.B2(DDR_WEN) U32.L3(WEN)
DISEN: J1.31 RP4.10
EMU2: J12.17(EMU2) TP20.1
EMU3: J12.18(EMU3) TP18.1
EMU4: J12.19(EMU4) TP22.1
EMU_RSTN: C183.1 J12.15(SRST) R97.1(P1)
ETH1_INTN: R122.1(P1) R123.2(P2) R124.1(P1) U23.5(INT)
ETH1_RBIAS: R146.2(P2) U23.9(RBIAS)
ETH1_RXCLK: R208.1(P1) R209.2(P2) U23.33(RX_CLK)
ETH1_RXD0: R204.1(P1) R205.2(P2) U23.31(RXD0)
ETH1_RXD1: R202.2(P2) R203.1(P1) U23.30(RXD1)
ETH1_RXD2: R68.2(P2) R69.1(P1) U23.28(RXD2)
ETH1_RXD3: R70.2(P2) R71.1(P1) U23.27(RXD3)
ETH1_RXDV: R206.1(P1) R207.2(P2) U23.32(RX_DV)
ETH2_INTN: R20.1(P1) R21.1(P1) R22.1(P1) U24.5(INT)
ETH2_RBIAS: R145.2(P2) U24.9(RBIAS)
ETH2_RXCLK: R199.2(P2) R200.1(P1) U24.33(RX_CLK)
ETH2_RXD0: R195.1(P1) R196.2(P2) U24.31(RXD0)
ETH2_RXD1: R193.2(P2) R194.1(P1) U24.30(RXD1)
ETH2_RXD2: R64.2(P2) R65.1(P1) U24.28(RXD2)
ETH2_RXD3: R66.2(P2) R67.1(P1) U24.27(RXD3)
ETH2_RXDV: R197.1(P1) R198.2(P2) U24.32(RX_DV)
ETH_MDIO_CLK: R147.1(P1) U24.1(MDC)
ETH_MDIO_DATA: R148.1(P1) U24.48(MDIO)
ETH_RESETN: R26.2(P2) R47.1(P1) U6.4(Y) U23.2(R\S\T\) U24.2(R\S\T\)
ETHER2_D0N: J7.10 U24.12(TRXN0)
ETHER2_D0P: J7.9 U24.11(TRXP0)
ETHER2_D1N: J7.8 U24.15(TRXN1)
ETHER2_D1P: J7.7 U24.14(TRXP1)
ETHER2_D2N: J7.6 U24.18(TRXN2)
ETHER2_D2P: J7.5 U24.17(TRXP2)
ETHER2_D3N: J7.4 U24.21(TRXN3)
ETHER2_D3P: J7.3 U24.20(TRXP3)
ETHER_D0N: J6.10 U23.12(TRXN0)
ETHER_D0P: J6.9 U23.11(TRXP0)
ETHER_D1N: J6.8 U23.15(TRXN1)
ETHER_D1P: J6.7 U23.14(TRXP1)
ETHER_D2N: J6.6 U23.18(TRXN2)
ETHER_D2P: J6.5 U23.17(TRXP2)
ETHER_D3N: J6.4 U23.21(TRXN3)
ETHER_D3P: J6.3 U23.20(TRXP3)
EXP_PB_POWERON: R112.1(P1) SW5.3 SW5.4 U25.33(PWRON)
F_ADBUS0: R75.2(P2) U28.16(ADBUS0)
F_ADBUS1: R227.2(P2) U28.17(ADBUS1)
F_ADBUS2: R228.2(P2) U28.18(ADBUS2)
F_ADBUS3: R79.2(P2) U28.19(ADBUS3)
F_ADBUS4: R229.2(P2) U28.21(ADBUS4)
F_ADBUS5: R78.2(P2) U28.26(ACBUS0)
F_ADBUS6: R230.2(P2) U28.23(ADBUS6)
F_ADBUS7: R77.2(P2) U28.30(ACBUS4)
F_EECS: R76.2 U9.5(CS) U28.63(EECS)
F_EEDATA: R81.1(P1) U9.3(DIN) U28.61(EEDATA)
F_EEDOUT: R81.2(P2) R83.2 U9.1(DOUT)
F_EESK: R82.2 U9.4(SK) U28.62(EESK)
FT_DM: U16.28(USBDM_DN1) U28.7(DM)
FT_DP: U16.1(USBDP_DN1) U28.8(DP)
FT_REF: R214.2 U28.6(REF)
FT_RESETN: R221.1(P1) U28.14(RESET#)
FT_SRESET: R16.2 R78.1(P1) U4.1(A)
FT_SRESETB: R17.2(P2) U5.6(1Y)
FT_SRESETN: U4.4(Y) U5.1(1A)
FT_VBUS: R110.1 U4.2(B) U16.7(PRTPWR1) U28.59(BCBUS7)
GPIO_KEY1: C243.1 R215.2(P2) SW3.3 SW3.4 U26.T17(GPMC_WAIT0)
GPIO_KEY2: C220.1 R165.2(P2) SW1.3 SW1.4 U26.T7(GPMC_OEN_REN)
GPIO_KEY3: C228.1 R172.2(P2) SW2.3 SW2.4 U26.R7(GPMC_ADVN_ALE)
GPIO_KEY4: C263.1 R231.2(P2) SW4.3 SW4.4 U26.T6(GPMC_BEN0_CLE)
HD_SPKRM: TP21.1 U31.22(HPRCOM)
HD_SPKRP: C185.1 U31.23(HPROUT)
HS_IND: R14.2(P2) U16.16(HS_IND)
HS_SPKRM: TP24.1 U31.19(HPLCOM)
HS_SPKRP: C181.1 U31.18(HPLOUT)
HUB_BIAS: R99.1 U16.26(RBIAS)
HUB_USBDM_UP: L1.2 U16.21(USBDM_UP)
HUB_USBDP_UP: L1.1 U16.22(USBDP_UP)
I2C_SCL_AUDIO: R232.1(P1) U31.1(SCL)
I2C_SDA_AUDIO: R233.1(P1) U31.2(SDA)
JTAG_EMU0: J12.13(EMU0) R90.2 R230.1(P1) U26.C14(EMU0///////GPIO3_7)
JTAG_EMU1: J12.14(EMU1) R77.1(P1) R234.1 U26.B14(EMU1///////GPIO3_8)
JTAG_TCK: R75.1(P1) R91.2(P2) R92.2(P2) U26.A12(TCK)
JTAG_TDI: J12.3(TDI) R227.1(P1) U26.B11(TDI)
JTAG_TDO: J12.7(TDO) R228.1(P1) U26.A11(TDO)
JTAG_TMS: J12.1(TMS) R79.1(P1) U26.C11(TMS)
JTAG_TRSTN: J12.2(TRSTN) R229.1(P1) R235.1 U26.B10(TRSTN)
KEYPAD_PWRA: R115.2(P2) SW1.1 SW1.2 SW2.1 SW2.2 SW4.1 SW4.2
LCD_BACKLIGHTEN: Q1.G(GATE) R219.2(P2) U26.C12(MCASP0_AHCLKR)
LCD_CAP_TOUCH_WAKE: R84.2(P2) R128.2(P2) U26.V12(GPMC_CLK)
LED+: C75.1 J1.2 U7.9(OUT)
LED-: J1.1 R63.2(P2) U7.5(FB)
MMC1_CLK: A1.16(SDIO_CLK/SPI_C) R184.1(P1) R220.1(P1)
MMC1_CMD: A1.15(SDIO_CMD/SPI_D) R57.1(P1) U26.V9(GPMC_CSN2)
MMC1_D0: A1.17(SDIO_D0/SPI_DOUT) R58.1(P1) U26.U7(GPMC_AD0)
MMC1_D1: A1.18(SDIO_D1) R183.1(P1) U26.V7(GPMC_AD1)
MMC1_D2: A1.14(SDIO_D2) R185.1(P1) U26.R8(GPMC_AD2)
MMC1_D3: A1.19(SDIO_D3/SPI_CS) R182.1(P1) U26.T8(GPMC_AD3)
NC0: U10.2(NC0)
NC1: U10.3(NC1)
NON_REM1: R118.1 R119.2 U16.13(NON_REM1)
NON_REM2: R12.2(P2) R13.1 TP1.1 U16.19(SUSP_IND/NON_REM0)
PHY2_LED_10/100N: C237.1 U24.26(LED_LINK10_100)
PHY2_LED_1000N: C81.1 R9.1 R61.2(P2) U24.24(LED_LINK1000)
PHY2_LED_ACTN: C68.1 R8.1 R62.2(P2) U24.23(LED_ACT)
PHY_LED_10/100N: C240.1 U23.26(LED_LINK10_100)
PHY_LED_1000N: C229.1 R7.1 R60.2(P2) U23.24(LED_LINK1000)
PHY_LED_ACTN: C226.1 R6.1 R53.2(P2) U23.23(LED_ACT)
PHY_PPS2/GPIO: R181.1(P1) U24.22(PPS)
PHY_PPS/GPIO: R176.1(P1) U23.22(PPS)
PLLFILT: C7.1 U16.25(PLLFILT)
PMIC_GPIO: R59.2 U25.39(GPIO_CKSYNC)
PMIC_GPIO_RTC: C191.1 R107.1(P1) R108.1(P1) U19.6(2B)
PMIC_I2C_SCL: R139.1(P1) U25.9(SCL_SCK)
PMIC_I2C_SDA: R140.1(P1) U25.8(SDA_SDI)
PMIC_INT1: R28.1(P1) R128.1(P1) U25.45(INT1)
PMIC_PWRHOLD: R27.1(P1) U25.1(PWRHOLD)
PMIC_RESETOUTN: R49.2(P2) U25.40(NRESPWRON) U26.B15(PWRONRSTN)
PMIC_SLEEP: TP9.1 U25.37(SLEEP)
PMICSR_I2C_SCL: R137.1(P1) U25.11(SCLSR_EN1)
PMICSR_I2C_SDA: R138.1(P1) U25.10(SDASR_EN2)
PWR_SMPS1: L11.1 U25.35(SW1)
PWR_SMPS1_FB: R201.2(P2) R223.2(P2) U25.32(VFB1)
PWR_SMPS2: L10.1 U25.42(SW2)
PWR_SWIO: L8.1 U25.14(SWIO)
PWR_VDDIO: R144.2(P2) U25.12(VDDIO)
REFIN_DDR: C171.1 R93.1 R95.1 U14.1(REFIN)
RESETN: C189.1 R106.1(P1) U16.17(R\E\S\E\T\)
RGMII1_INT: R122.2(P2) U26.U6(GPMC_WEN)
RGMII1_TXCLK: R134.2(P2) U26.K18(MII1_TXCLK)
RGMII1_TXD0: R135.2(P2) U26.K17(MII1_TXD0)
RGMII1_TXD1: R130.2(P2) U26.K16(MII1_TXD1)
RGMII1_TXD2: R136.2(P2) U26.K15(MII1_TXD2)
RGMII1_TXD3: R133.2(P2) U26.J18(MII1_TXD3)
RGMII1_TXEN: R129.2(P2) U26.J16(MII1_TXEN)
RGMII2_INT: R20.2(P2) U26.F16(USB0_DRVVBUS)
RGMII2_TXCLK: R168.2(P2) U26.U15(GPMC_A6)
RGMII2_TXD0: R174.2(P2) U26.V15(GPMC_A5)
RGMII2_TXD1: R51.2(P2) U26.R14(GPMC_A4)
RGMII2_TXD2: R180.2(P2) U26.T14(GPMC_A3)
RGMII2_TXD3: R192.2(P2) U26.U14(GPMC_A2)
RGMII2_TXEN: R56.2(P2) U26.R13(GPMC_A0)
RSVD3: R109.1(P1) U16.15(VSS)
RTC_PORZ: R125.2(P2) U19.3(2Y) U26.B5(RTC_PWRONRSTN)
RTCK: J12.9(TCKRTN) R92.1(P1)
SS: C64.1 R48.1(P1) R50.2(P2) U7.3(SS)
SW3: U25.31(SW3)
SYS_WARMRESETN: C279.1 R17.1(P1) R87.2(P2) R97.2(P2) R191.1(P1) SW7.3 SW7.4 U6.2(A) U26.A10(WARMRSTN)
TCK: J12.11(TCK) R91.1(P1)
TDIS: J12.4(TDIS) R236.2(P2)
USB0_DM: U16.2(USBDM_DN2) U26.N18(USB0_DM)
USB0_DP: U16.3(USBDP_DN2) U26.N17(USB0_DP)
USB0_ID: TP4.1 U26.P16(USB0_ID)
USB0_VBUS: C18.1 R15.1(P1) U5.4(2Y) U26.P15(USB0_VBUS)
USB0_VBUS_PWR: U5.3(2A) U16.11(PRTPWR2)
USB1_CONN_DM: J5.2(DM) L2.3 U17.2(D-)
USB1_CONN_DP: J5.3(DP) L2.4 U17.1(D+)
USB1_DM: L2.2 U26.R18(USB1_DM)
USB1_DP: L2.1 U26.R17(USB1_DP)
USB1_ID: R143.2(P2) U26.P17(USB1_ID)
USB5V_FB: R18.2(P2) R19.1(P1) U20.E3(FB)
USB_DC: C2.1 C188.1 J3.1(VBUS) R103.2(P2) U15.6(VBUS)
USBDM_UP: J3.2(DM) L1.3 U15.2(D-)
USBDP_UP: J3.3(DP) L1.4 U15.1(D+)
VADDL_PHY: C40.1 C48.1 C54.1 C66.1 FB17.1 U23.8(AVDDL#8) U23.13(AVDDL#13) U23.19(AVDDL#19) U23.44(AVDDL#44)
VADDL_PHY2: C36.1 C47.1 C58.1 C65.1 FB14.1 U24.8(AVDDL#8) U24.13(AVDDL#13) U24.19(AVDDL#19) U24.44(AVDDL#44)
VAUX1: C55.1 C56.1 C221.1 U25.46(VAUX1) U26.N16(VDDA1P8V_USB0) U26.R16(VDDA1P8V_USB1)
VAUX2: C31.1 FB6.2 U25.48(VAUX2)
VAUX33: C176.1 C212.1 R27.2(P2) R28.2(P2) R96.1 R144.1(P1) R240.2(P2) U14.10(VIN) U25.4(VAUX33)
VCOM_BAT: C135.1 C215.1 C257.1 L12.2 R224.2(P2) U22.1(VIN) U27.4(OUT)
VCOM_BATFB: C257.2 R222.2(P2) R224.1(P1) U27.5(FB)
VDAC: C44.1 C61.1 C62.1 C87.1 C227.1 C236.1 U25.22(VDAC) U26.E6(VDDS#E6) U26.E14(VDDS#E14) U26.F9(VDDS#F9) U26.K13(VDDS#K13) U26.N6(VDDS#N6) U26.P9(VDDS#P9) U26.P14(VDDS#P14)
VDIG1: C210.1 FB9.2 U25.7(VDIG1)
VDIG2: C53.1 C59.1 C72.1 C84.1 C95.1 C98.1 C211.1 U25.5(VDIG2) U26.D10(VDDS_SRAM_MPU_BB) U26.E7(VDDS_PLL_DDR) U26.E9(VDDS_SRAM_CORE_BG) U26.H15(VDDS_PLL_MPU) U26.R10(VDDS_PLL_CORE_LCD) U26.R11(VDDS_OSC)
VETH2_AVDD_3_3: C204.1 C218.1 FB15.2 R196.1(P1) U24.16(AVDD33)
VETH2_LX: L3.2 U24.3(LX)
VETH2_VDDIO: C71.1 R54.2(P2) U24.29(VDDIO_REG)
VETH_AVDD_3_3: C219.1 C222.1 FB16.2 U23.16(AVDD33)
VETH_LX: L5.2 U23.3(LX)
VETH_VDDIO: C73.1 R25.1(P1) R30.2(P2) R55.2(P2) U23.29(VDDIO_REG)
VMMC: C52.1 C78.1 C213.1 FB2.2 FB3.2 FB4.2 FB5.2 R120.2(P2) U3.1(EN) U7.6(EN) U13.1(EN) U25.2(VMMC) U26.N15(VDDA3P3V_USB0) U26.R15(VDDA3P3V_USB1) U27.1(EN)
VPLL: C232.1 FB7.2 U25.24(VPLL)
VPP: U26.M5(VPP)
VPWRIN_JCK: D8.2(ANODE) U30.2
VPWRIN_PREFUSE: D8.1(CATHODE) F1.1
VREFP_ADC: C88.1 C89.1 R73.2(P2) U26.B9(VREFP)
VRTC: C192.1 C197.1 C239.1 R23.2(P2) R59.1 R108.2(P2) R121.1(P1) R175.2(P2) R178.1(P1) U19.1(2A) U19.2(2B) U19.5(2A) U19.8(VCC) U26.D7(VDDS_RTC)
VRTC_PMIC: C238.1 R23.1(P1) U25.19(BOOT1) U25.29(VRTC)
VTT_DDR: C141.1 C182.1 C186.1 R241.2 RP5.9 RP5.10 RP5.11 RP5.12 RP5.13 RP5.14 RP5.15 RP5.16 RP6.9 RP6.10 RP6.11 RP6.12 RP6.13 RP6.14 RP6.15 RP6.16 RP7.9 RP7.10 RP7.11 RP7.12 RP7.13 RP7.14 RP7.15 RP7.16 U14.3(VO) U14.5(VOSNS)
VUSB_VBUS1: C190.1 C193.1 J5.1(VBUS) R126.1 U17.6(VBUS) U18.6(OUT#6) U18.7(OUT#7) U18.8(OUT#8)
WOL_INT2: R175.1(P1) R189.1(P1) U24.40(WOL_INT)
WOL_INT_1: R173.1(P1) R178.2(P2) U23.40(WOL_INT)
XTALIN: C6.2 R10.2(P2) U16.24(XTALIN/CLKIN) Y3.3
XTALIN_2: C208.2 R24.1(P1) U24.7(XTLI) Y1.2
XTALOUT: C4.2 R10.1(P1) U16.23(XTALOUT) Y3.1
XTALOUT_2: C209.2 U24.6(XTLO) Y1.1
XTIN: C234.2 U28.2(XTIN) Y5.3(X3)
XTOUT: C233.2 U28.3(XTOUT) Y5.1(X1)
N17107785: C225.1 U25.18(VREF)
N17257600: R220.2(P2) U26.U9(GPMC_CSN1)
N17308459: R171.1(P1) U26.A17(SPI0_SCLK)
N17308818: R52.2(P2) U26.D14(XDMA_EVENT_INTR1)
N17308847: R186.2(P2) U26.A15(XDMA_EVENT_INTR0)
N17365914: R132.2(P2) U26.G17(MMC0_CLK)
N17619435: R181.2(P2) TP8.1
N17619707: R169.2(P2) U24.41(SD)
N17686170: R210.1(P1) R211.1(P1) U26.C5(EXT_WAKEUP)
N17710761: R226.2(P2) U26.J3(DDR_VTP)
N21001559: R29.2(P2) R117.1(P1) SW6.3 SW6.4
N21001565: R166.2(P2) R167.2(P2) SW6.1 SW6.2
N21499158: C202.2 U23.6(XTLO) Y4.1
N21499159: C201.2 U23.7(XTLI) Y4.2
N21499217: R176.2(P2) TP7.1
N21499246: R170.2(P2) U23.41(SD)
N21689199: R94.2 U32.L8(ZQ)
N21748558: TP10.1 U26.A3(RESERVED)
N21748687: R218.2 U26.B4(RTC_KALDO_ENN)
N21817883: D3.2(ANODE) R113.1(P1)
N21817885: D3.1(CATHODE) Q3.D(DRAIN)
N21817914: D4.1(CATHODE) Q2.D(DRAIN)
N21817935: D4.2(ANODE) R111.1(P1)
N21817961: D2.1(CATHODE) Q5.D(DRAIN)
N21817965: D2.2(ANODE) R114.1(P1)
N21817990: D1.1(CATHODE) Q4.D(DRAIN)
N21818011: D1.2(ANODE) R116.1(P1)
N21818396: R74.1(P1) U8.7(WP)
N21904036: L4.1 U20.B1(L1#B1) U20.B2(L1#B2)
N21904046: L4.2 U20.D1(L2#D1) U20.D2(L2#D2)
N21904056: C198.1 U20.A3(VINA) U20.B3(VINA1) U20.C4(P\S\) U20.D4(VSEL)
N21930375: A1.2(VBAT#2) A1.3(VBAT#3) C136.1 L12.1
N21930388: A1.12(VIO) C230.1 L7.2
N21930620: A1.21(SLEEP_CLK) R187.1(P1) R188.1(P1)
N21930813: A1.40(2.4G_ANT) R239.1(P1)
N21931209: J10.4(OUT) L14.1(P1)
N21931218: J10.1(IN) R239.2(P2)
N21931238: L13.1 L14.2(P2) L15.2
N22083094: R244.1(P1) U10.9(INT2)
N22083163: R85.1(P1) U10.7(SDO/SA0)
N22104394: C245.2 R213.2(P2) R216.1(P1) Y6.1
N23618396: ANT1.1(FEED) L15.1
N23679698: C181.2 J13.3(P3)
N23719034: C146.1 U31.3(LINE1LP)
N23719056: C150.1 U31.4(LINE1LM)
N23719058: C153.1 U31.5(LINE1RP)
N23719070: C155.1 U31.6(LINE1RM)
N23719098: C163.1 U31.10(LINE2RM)
N23719102: C161.1 U31.27(MONO_LOP)
N23719106: C157.1 U31.28(MONO_LOM)
N23719110: C160.1 U31.9(LINE2RP)
N23719153: TP14.1 U31.35(GPIO1)
N23719155: TP16.1 U31.34(GPIO2)
N23719175: C164.1 U31.11(MIC3L)
N23719177: C166.1 U31.14(MIC3R)
N23760521: C156.1 U31.7(LINE2LP)
N23760525: C159.1 U31.8(LINE2LM)
N23829528: C162.1 U13.5(FB)
N23838237: C19.1 U3.5(FB)
N24290596: C167.1 R88.2 R89.2
N24349607: J6.D1 R6.2
N24349674: J6.D4 R7.2
N24351121: J7.D1 R8.2
N24351236: J7.D4 R9.2
N24874310: R96.2 TP23.1 U14.9(PGOOD)
N26901426: D5.2(ANODE) R240.1(P1)
N27067217: J9.1 U30.1
N27225292: C249.2 R217.2(P2) Y7.1
N27225472: R121.2(P2) U21.5(OUT)
N27258497: R107.2(P2) U19.7(2Y)
N27371597: C185.2 J13.2(P2)
N27429071: J2.5 R80.1(P1)
N27429091: J2.6 R84.1(P1) R225.1(P1)
N269460692: Q1.D(DRAIN) R48.2(P2)
N2208308711: R86.1(P1) U10.8(CS)

Pads without a net: A1 11 33 34; ANT1 2; J1 35; J2 7 8; J3 4; J6 2 M1 M2; J7 2 M1 M2; J12 6; J13 10; NOREF 1; NOREF#2 1; NOREF#4 1; NOREF#5 1; NOREF#6 1; NOREF#7 1; NOREF#8 1; NOREF#9 1; NOREF#10 1; NOREF#11 1; NOREF#12 1; NOREF#13 1; NOREF#14 1; NOREF#15 1; R212 3 4; R238 3 4; RP4 1 2 3 14 15 16; U1 4 9; U2 2 5; U6 1; U15 3 5; U16 5 8 12; U17 3 5; U21 4; U23 42 43 45 46; U24 25 42 43 45 46; U25 21 25 30 38; U26 C6 D3; U28 22 24 27 29 33 34 36 43 44 45 46 48 52 53 54 55 57 58 60; U29 11; U31 12 13 29 30 31 32 47 48; U32 J1 J9 L1 L9 M7; Y2 2 3 4 5 8 9 10 11; Y3 2 4; Y5 2 4; Y6 2 4; Y7 2 3

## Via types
v1: diameter 0.508, hole 0.254, TOP to BOTTOM, 1519 vias
v2: diameter 0.457, hole 0.203, TOP to BOTTOM, 342 vias

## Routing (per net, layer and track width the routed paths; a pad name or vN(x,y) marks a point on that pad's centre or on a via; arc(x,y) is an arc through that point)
AGND_AUD: length 12.5
  TOP w0.381: v1(47.53,13.82) 47.3,13.59 C150.2 C155.2 ; v1(46.86,9.44) 46.61,9.69 C163.2 C159.2
  BOTTOM w0.254: U31.15 41.58,10.46 v1(40.85,11.2) ; U31.26 37.58,9.96 v1(37.8,10.18) ; U31.20 39.08,8.13 38.86,7.91 v1(38.86,7.87) 38.58,8.15 U31.21
  BOTTOM w0.508: v1(34.5,10.11) 34.12,9.73 C278.2 ; C280.2 36.83,5.49 36.91,5.41 v1(36.91,5.16)
  vias: v1(37.68,4.39) v1(37.8,14.24) v1(37.8,13.23) v1(37.8,12.21) v1(37.8,11.2) v1(38.82,14.24) v1(38.82,13.23) v1(38.82,12.21) v1(38.82,11.2) v1(38.82,10.18) v1(39.83,14.24) v1(39.83,13.23) v1(39.83,12.21) v1(39.83,11.2) v1(39.83,10.18) v1(40.6,4.78) v1(40.85,14.24) v1(40.85,13.23) v1(40.85,12.21) v1(43.14,4.97)
DGND: length 708.2
  TOP w0.203: v1(31.87,32.42) 31.87,32.46 32.31,32.9 J1.3 ; C78.2 70.63,36.39 70.71,36.39 70.91,36.59 70.91,36.78 v2(71.14,37.01)
  TOP w0.254: v2(74.34,30.61) 73.82,30.09 C112.2 C111.2 ; v2(77.91,7.2) 78.06,7.05 C172.2 ; v1(23.37,32.89) 22.86,32.89 22.67,33.08 Y2.6 ; C147.2 75.17,14.05 v2(74.71,13.6) 74.71,13.69 ; v1(71.52,6.95) 71.38,6.81 C175.2 ; C173.2 73.21,7.09 v2(73.11,7.19) ; U7.8 U7.PAD ; C168.2 70.48,8.57 v2(70.71,8.8) ; C120.2 C118.2 C108.2 ; v1(86.54,2.82) 86.56,2.8 U14.4 88.78,2.8 U14.11 U14.8 ; J1.36 48.81,32.88 v1(48.49,32.56) ; C98.2 77.87,32.86 77.91,32.82 v2(78.34,32.21) ; v2(72.31,8.8) 72.32,8.8 C165.2 ; v2(70.71,13.6) 70.61,13.7 C148.2 ; v1(28.61,39.36) 28.7,39.45 U7.7 ; v2(75.44,6.96) 75.65,6.76 75.65,6.58 R94.1 ; 94.89,18.65 94.89,18.9 v1(94.74,19.04) ; C142.2 78.54,16.46 v1(78.54,16.76) ; U7.4 27.65,39.45 ; C30.2 75.71,44.2 v1(75.57,44.06) ; C121.2 73.26,28.47 v2(73.54,28.19) ; v2(69.91,7.99) 69.81,8.1 C169.2 ; C114.2 C113.2 74.47,29.94 v2(74.34,29.81) ; C110.2 C109.2 71.69,30.07 v2(71.14,30.61) ; v1(45.02,32.58) 45.31,32.87 J1.29 ; v2(80.32,6.98) 80.16,6.83 C174.2 ; C119.2 71.66,28.75 71.46,28.55
  TOP w0.305: v1(41.78,44.45) R40.1 R39.1 ; v1(45.85,44.45) R44.1 R43.1 ; R41.1 R42.1 v1(43.81,44.45) ; C80.2 73.39,36.07 v2(72.74,35.41) 72.39,35.76 72.19,35.76 C79.2 ; v1(33.66,44.45) R32.1 R31.1 ; C102.2 73.11,30.99 v2(72.74,30.61) ; U10.16 v1(97.91,17.52) ; U10.12 U10.13 96.91,15.75 v1(97.66,15.75) ; v2(74.34,34.61) 74.34,35.04 74.61,35.31 75.03,35.31 ; v1(39.75,44.45) R38.1 R37.1 ; v1(95,14.99) 95.39,15.38 U10.10 ; v2(71.14,33.81) 70.8,33.47 C96.2 ; v1(35.69,44.45) R34.1 R33.1 ; R45.1 R46.1 v1(47.88,44.45) ; 94.89,18.65 U10.5 ; v2(74.34,33.81) 74.1,33.81 73.94,33.66 C92.2 ; v1(37.72,44.45) R36.1 R35.1
  TOP w0.381: U11.14 v1(53.21,14.65) ; v1(84.66,47.65) 85.07,48.06 85.76,48.06 85.96,47.85 U6.3 ; v1(52.58,13.72) 52.3,14 U11.15 ; v1(54.97,14.82) 54.96,14.82 55.14,14.65 U11.3 ; C91.2 72.32,33.71 72.43,33.81 v2(72.74,33.81) ; C59.2 73.84,40.64 C45.2 ; v2(71.14,30.61) 71.13,30.61 C116.2 ; U2.4 101.45,58.3 101.47,58.32 v1(101.76,58.32) ; U12.8 58.74,10.91 v1(58.6,11.05) ; U5.2 v1(44.7,51.83) ; C58.2 53.4,39.37 53.72,39.7 v1(54.41,39.7) ; C57.2 77.57,40.46 v2(78.34,41.22) ; U11.9 v1(52.17,17.9) ; U12.15 v1(55.6,7.01) ; C94.2 76.08,33.99 75.31,33.99 v2(75.14,33.81) ; U12.2 58.95,7.01 v1(58.67,6.73) ; v1(110.19,47.83) 109.81,48.2 C25.2 ; C60.2 68.12,39.8 C50.2 68.12,41.41 67.95,41.58 v2(67.57,41.58) 67.07,41.08 C52.2 ; C86.2 76.89,35.56 C82.2 76.24,35.41 v2(75.94,35.41) ; C101.2 71.57,30.99 v2(71.14,31.41) 70.71,30.99 C100.2 ; U12.9 53.13,10.91 v1(52.77,10.56) ; v1(98.55,32.89) 98.55,32.64 98.3,32.39 R68.1 ; v1(91.69,34.16) 90.68,34.16 C93.2 ; C125.2 73.39,28.04 v2(73.54,28.19) ; v2(75.94,31.41) 75.6,31.75 C103.2 ; U12.14 v1(55.6,7.66) ; U1.5 v1(106.36,65.66) ; v1(55.25,17.9) U11.8 ; 75.03,35.31 C85.2
  TOP w0.508: v1(91.57,40) 92.64,40 C54.2 ; R95.2 C171.2 86.87,7.49 86.99,7.62 v1(86.99,7.87) ; v1(92.84,29.97) C107.2 C104.2 ; v1(101.87,30.81) 102.46,30.21 C115.2 ; v1(67.2,42.74) 67.2,43.45 67.64,43.89 67.78,43.89 C28.2 ; v1(14.81,52.02) 14.81,51.26 15.21,50.86 C21.2 15.69,50.86 16.08,51.26 v1(16.08,52.02) ; C45.2 v2(74.35,42.04) 74.93,41.46 C53.2 ; v1(33.4,13.59) 33.4,12.95 C154.2 ; v1(20.53,48.84) 20.91,48.84 21.16,49.1 R18.1 ; C29.2 74.41,44.31 74.8,44.7 v1(75.56,44.7) ; v1(91.58,6.42) 91.85,6.69 C176.2 92.59,6.69 93.34,6.69 v1(93.61,6.42) ; C27.2 81.78,46.4 v1(81.78,47.34) ; C16.2 45.34,55.25 v1(44.96,55.63) ; U3.6 111.69,58.62 v1(111,59.31) ; U3.6 v1(109.63,57.94) ; U3.6 113.7,57.94 v1(114,58.24) ; v1(85.25,42.24) 86.05,42.24 C44.2 ; v1(115.25,31.75) 115.26,31.77 C97.2 ; v1(88.01,35.56) 87.25,34.8 C87.2 C84.2 ; v2(63.32,27.43) 63.27,27.43 63.14,27.56 C127.2 C126.2 ; C162.2 26.48,10.11 26.3,10.29 26.29,10.29 26.16,10.41 v1(26.16,10.54) ; C138.2 v1(116.08,19.18) ; C12.2 v1(50.43,55.54) ; R70.1 v1(101.47,31.67) ; v1(87.76,37.42) 87.75,37.42 87.73,37.42 87.39,37.08 C72.2 ; v1(99.9,1.95) 99.9,2.85 C183.2 ; v1(22.56,37.54) 22.43,37.41 C70.2 ; v1(48.13,14.86) 48.56,14.86 C149.2 ; v1(80.68,16.41) 80.91,16.64 C141.2 v1(82.37,17.91) ; C13.2 46.54,55.75 46.55,55.77 v1(47.05,55.77) ; R14.1 v1(37.56,53.34) ; C41.2 97.72,41.46 v1(97.28,41.02) ; v1(29.21,29.34) J1.41 v1(27.62,31.04) ; R66.1 59.18,32.26 v1(59.18,31.84) ; C170.2 52.63,7.42 v1(52.63,8.08) ; FB10.2 34.59,19.62 v1(34.27,19.94) ; C71.2 v1(55.63,38.48) ; C55.2 C56.2 v2(71.94,40.77) ; C9.1 v1(82.04,59.06) ; v1(102.01,62.74) C3.2 v1(101.05,63.75) ; U4.3 v1(47,53.61) ; v1(97.28,38.48) 98.18,38.48 98.3,38.61 C66.2 ; C39.2 95.5,41.53 v1(96.01,41.02) 96.65,41.66 C40.2 ; v1(65.56,29.62) C105.2 C106.2 ; C61.2 81.46,40.39 v1(81.97,40.39) 82.48,40.39 C62.2 ; v1(30.48,67.54) FB1.1 v1(29.3,66.35) ; C47.2 58.17,40.26 57.46,40.26 v1(56.9,39.7) ; U8.1 v1(102.23,23.13) ; C19.2 v1(117.79,51.69) ; U8.4 106.05,20.22 v1(105.54,19.71) ; v1(62.19,12.14) 62.6,12.56 C158.2 ; v1(46.54,60.33) 46.54,60.76 46.34,60.96 C5.2 ; C90.2 65.18,34.65 65.17,34.63 v2(64.87,34.63) ; v1(88.24,15.65) 88.69,16.09 C140.2 ; v1(24.61,38.22) 24.63,38.22 24.63,38.22 23.51,38.22 23.04,38.7 22.97,38.7 R50.1 ; C48.2 98.3,40.77 v1(97.28,39.75) ; C4.1 v1(48.77,62.86) ; v1(92.84,28.96) 92.24,28.96 C123.2 92.12,28.07 v1(92.96,28.07) ; v1(102.18,1.95) 102.18,2.85 C184.1 ; v1(113.79,27.16) C132.2 v1(116.33,27.16) ; v2(82.1,35.92) 81.69,36.32 C83.2 ; J1.42 52.91,30.95 53.61,30.26 53.61,30.21 v1(54.31,29.51) ; C8.1 v1(72.6,59.7) ; U13.6 v1(30.94,6.05) ; U13.6 v1(28.6,4.8) ; U13.6 v1(33.25,4.8) ; C38.2 94.36,41.4 v1(94.74,41.02) ; C64.2 v1(25.41,37.79) ; v1(41.71,62.72) C2.2 v1(42.84,63.8) ; C117.2 57.67,29.32 57.31,28.96 v1(56.5,28.96) ; C65.2 57.92,38.61 57.79,38.48 v1(56.9,38.48) 57.15,38.23 C68.2 C81.2 ; C10.1 v1(87.25,59.06) ; C6.1 v1(51.11,59.44) ; v1(27.01,32.09) R63.1 v1(25.97,33.21) ; C36.2 56.26,41.66 v1(55.63,40.97) 55.12,41.53 C35.2 ; C151.2 v1(59.56,12.51) ; C23.2 25.48,48.25 v1(26.28,48.25) ; v1(93.99,1.85) 93.54,1.4 C187.2 ; FB8.2 86.27,28.83 86.4,28.71 v1(87.61,28.71) ; C37.2 57.4,41.53 v1(56.9,40.97) ; C14.2 48.22,55.63 v1(48.6,56.01) ; v1(43.82,55.63) 43.31,55.12 C15.2 ; v1(106.17,37.47) 106.54,37.1 C67.2 109.16,37.1 109.54,36.71 v1(109.54,36.71) ; v1(18.12,52.02) 18.12,51.26 17.72,50.86 C22.2 17.24,50.86 16.85,51.26 v1(16.85,52.02) ; R53.1 v1(103.08,37.47) ; v2(74.71,13.6) 74.16,13.6 C145.2 ; C124.2 v1(110.62,27.81) ; U13.3 31.2,11.35 v1(31.2,12.52) v1(31.2,13.41) ; C31.2 105.21,44.58 v1(105.47,44.83) ; v1(55.12,34.32) 55.44,34 55.44,33.11 55.47,33.07 55.77,32.77 56.01,32.77 R64.1 ; C180.2 v1(60.13,4.38) ; C1.2 v1(96.52,67.31) ; R12.1 v1(37.56,55.63) ; J2.2 63.51,24.41 63.47,24.45 63.47,23.05 v2(63.2,22.78) ; C18.2 72.23,52.03 v1(72.96,51.31) ; C137.2 v1(108.46,20.32) ; v1(54.46,41.1) 53.97,41.58 C34.2 ; C7.2 44.89,58.57 44.96,58.5 v1(44.96,57.91) ; C133.2 v1(40.32,25.98) ; v1(109.02,42.16) C43.2 109.87,41.91 109.87,40.91 R49.1 ; v1(58.17,34.8) R61.1 R62.1 ; C73.2 v1(96.01,38.48) ; v1(35.77,23.03) C134.2 34.02,23.03 v1(33.84,23.21) ; D5.1 v1(130.28,12.7) ; v1(92.58,18.03) R85.2 ; C32.2 123.58,42.62 v1(124.21,43.24) ; C24.2 v1(24.21,48.72) ; v1(104.77,23.13) U8.3 ; v1(18.24,36.65) 18.5,36.91 C69.2 ; v1(103.08,36.37) 102.98,36.37 R60.1 ; v1(42.67,56.77) C11.2 ; U9.2 v1(47.88,18.9) ; v1(25.74,20.65) 25.74,21.41 26.13,21.81 C135.2 26.61,21.81 27.01,21.41 v1(27.01,20.65) ; U8.2 v1(103.5,23.13) ; C17.1 v1(53.99,53.54)
  TOP w0.635: Q1.S 19.97,41.67 v1(19.34,41.05) ; 56.84,50.44 J7.1 ; J7.1 55.95,51.33 ; J7.1 57.73,51.33 ; v1(44.07,17.78) C139.2
  LY2_GND1 w0.635: J6.D3 91.31,63.63 ; J6.D3 90.43,62.76 ; J6.D3 92.18,62.76 ; J11.4 94.73,13.21 ; J11.4 93.73,12.2 ; J11.4 93.73,14.21 ; J11.4 92.72,13.21 ; TP2.1 34.16,54.69 ; TP2.1 33.1,53.62 ; TP2.1 34.16,52.55 ; TP2.1 35.23,53.62 ; 27.37,57.12 J5.4 ; J5.4 27.37,58.89 ; J5.4 26.48,58.01 ; J5.4 28.26,58.01 ; J6.1 78.81,52.21 ; J6.1 77.92,51.33 ; J6.1 79.7,51.33 ; J6.1 78.81,50.44 ; 77.74,63.91 J6.D2 ; J6.D2 78.62,64.79 ; J6.D2 77.74,65.66 ; J6.D2 76.87,64.79 ; 56.84,50.44 J7.1 ; J7.1 57.73,51.33 ; J7.1 56.84,52.21 ; J7.1 55.95,51.33 ; TP13.1 99.96,18.87 ; TP13.1 98.89,19.94 ; TP13.1 98.89,17.8 ; TP13.1 97.82,18.87 ; 54.9,64.79 J7.D2 ; J7.D2 56.65,64.79 ; J7.D2 55.77,65.66 ; J7.D2 55.77,63.91 ; J8.1 41.77,47.24 ; J8.1 40.77,46.24 ; J8.1 40.77,48.25 ; J8.1 39.76,47.24 ; J7.D3 69.34,63.63 ; J7.D3 68.46,62.76 ; J7.D3 70.21,62.76
  LY2_GND1 w1.016: 119.38,8.06 MH4.1 ; MH4.1 123.47,12.15 ; MH4.1 123.47,8.06 ; MH4.1 119.38,12.15 ; MH3.1 12.35,12.15 ; MH3.1 8.26,12.15 ; MH3.1 8.26,8.06 ; MH3.1 12.35,8.06 ; 121.43,58.08 MH2.1 ; MH2.1 121.43,63.72 ; MH2.1 124.25,60.9 ; MH2.1 118.61,60.9 ; MH1.1 10.3,63.47 ; MH1.1 12.87,60.9 ; MH1.1 10.3,58.34 ; MH1.1 7.73,60.9
  LY7_GND2 w0.635: J7.D3 69.34,63.63 ; J7.D3 68.46,62.76 ; J7.D3 70.21,62.76 ; J11.4 94.73,13.21 ; J11.4 92.72,13.21 ; J11.4 93.73,14.21 ; J11.4 93.73,12.2 ; J6.1 79.7,51.33 ; J6.1 78.81,52.21 ; J6.1 78.81,50.44 ; J6.1 77.92,51.33 ; J5.4 28.26,58.01 ; J5.4 26.48,58.01 ; J5.4 27.37,58.89 ; J5.4 27.37,57.12 ; J8.1 40.77,48.25 ; J8.1 40.77,46.24 ; J8.1 41.77,47.24 ; J8.1 39.76,47.24 ; 98.89,17.8 TP13.1 ; TP13.1 97.82,18.87 ; TP13.1 99.96,18.87 ; TP13.1 98.89,19.94 ; J7.1 56.84,52.21 ; J7.1 55.95,51.33 ; J7.1 56.84,50.44 ; J7.1 57.73,51.33 ; J6.D3 92.18,62.76 ; J6.D3 91.31,63.63 ; J6.D3 90.43,62.76 ; J6.D2 78.62,64.79 ; J6.D2 76.87,64.79 ; J6.D2 77.74,63.91 ; J6.D2 77.74,65.66 ; TP2.1 34.16,54.69 ; TP2.1 35.23,53.62 ; TP2.1 34.16,52.55 ; TP2.1 33.1,53.62 ; J7.D2 56.65,64.79 ; J7.D2 55.77,63.91 ; J7.D2 54.9,64.79 ; J7.D2 55.77,65.66
  LY7_GND2 w1.016: 121.43,58.08 MH2.1 ; MH2.1 121.43,63.72 ; MH2.1 118.61,60.9 ; MH2.1 124.25,60.9 ; MH1.1 12.87,60.9 ; MH1.1 7.73,60.9 ; MH1.1 10.3,63.47 ; MH1.1 10.3,58.34 ; MH3.1 12.35,8.06 ; MH3.1 8.26,12.15 ; MH3.1 8.26,8.06 ; MH3.1 12.35,12.15 ; 119.38,12.15 MH4.1 ; MH4.1 119.38,8.06 ; MH4.1 123.47,12.15 ; MH4.1 123.47,8.06
  BOTTOM w0.102: U20.D3 U20.E4
  BOTTOM w0.14: 71.14,37.01 v2(71.14,37.01)
  BOTTOM w0.203: v1(116.52,34.92) 115.85,35.6 U25.26 ; v1(115.21,39.27) 115.84,38.64 U25.20 ; U20.D3 U20.C3 U20.C2 U20.C1 v1(24.21,48.72) ; 112.65,37.57 U25.34 ; U25.15 115.63,40.64 ; 117.75,39.84 U25.17 115.63,39.84 ; 112.04,39.44 U25.43 ; U20.B4 20.8,49.12 v1(20.53,48.84)
  BOTTOM w0.254: U32.T1 79.91,15.65 v1(80.68,16.41) ; C225.2 118.39,39.57 118.11,39.84 117.75,39.84 ; U31.42 39.58,16.47 v1(39.75,16.64) 40.08,16.31 U31.43 ; U32.P1 78.31,15.26 78.54,15.49 v1(78.54,16.76) ; v2(66.17,26.19) 66.71,26.19 U26.V1 ; U20.E4 v1(20.66,47.92) ; U29.6 54.92,24.17 v1(55.04,24.05) ; U15.4 v1(38.51,63.38) ; U19.4 112.03,48.27 v1(111.59,47.83) ; D6.2 v1(66.99,45.97)
  BOTTOM w0.305: U26.M9 v2(71.94,33.01) U26.M10 ; U28.5 v1(44.89,30.58) ; U26.G11 v2(75.14,33.81) 74.74,33.41 U26.H10 ; U26.J9 v2(74.34,32.21) U26.H9 ; U26.A18 v1(79.94,40.21) ; U28.1 v1(45.02,32.58) ; U26.G9 75.3,32.37 75.3,32.05 U26.G8 v2(75.94,31.41) U26.F8 ; v2(72.74,33.01) U26.K9 ; U26.L11 72.34,34.22 v2(72.74,34.61) U26.K11 ; U26.H12 v2(74.34,34.61) U26.J11 ; U26.N10 70.74,33.42 v2(71.14,33.81) 70.74,34.21 U26.N11 ; U32.B3 v2(68.31,12.79) ; U26.K10 v2(72.74,33.81) 72.34,33.42 U26.L10 ; v2(71.14,35.41) U26.M12 ; U28.32 v1(36.92,24.46) ; v2(74.34,33.81) 73.94,33.41 U26.J10 ; U26.V18 66.45,40.11 v2(64.62,40.11) ; U26.M8 v2(71.14,31.41) U26.N7 ; U28.15 45.29,25.58 v1(44.83,26.04) 44.83,26.05 45.36,26.58 U28.13 ; U26.J6 v2(74.34,29.81) U26.H6 ; U26.M14 71.14,37.01 U26.N14 ; U26.J8 v2(74.34,31.41) U26.H8 ; U28.10 v1(47.81,28.08) 47.47,27.74 47.45,27.74 47.35,27.64 47.32,27.64 47.26,27.58 U28.11 ; U28.51 v1(37.92,32.74) ; v2(72.74,30.61) U26.K7 ; U28.35 v1(36.3,26.08) ; U26.J7 v2(74.34,30.61) U26.H7 ; U28.25 v1(40.42,24.51) ; v1(47.05,55.77) 47.03,55.77 47.01,55.79 U16.6 ; U26.L13 v2(72.74,35.41) 72.34,35.02 U26.L12 ; U28.47 v1(36.3,32.08) ; U26.M6 v2(71.14,30.61) U26.M7 ; v2(75.94,35.41) U26.G12
  BOTTOM w0.381: U32.D1 70.03,14.27 70.03,15.54 v1(69.09,16.48) ; R68.1 98.19,32.39 98.55,32.75 v1(98.55,32.89) ; J4.6 v1(111.12,67.65) ; U26.A1 80.53,26.02 80.87,26.02 v2(81.11,25.78) ; U32.E2 v2(70.71,13.6) ; U32.G8 v2(72.31,8.8) ; C255.2 v1(58.04,25.15) ; U29.15 52.32,18.92 v1(52.58,18.67) 52.97,19.07 U29.14 ; C234.1 44.58,35.93 45.02,35.48 v1(45.02,32.58) ; v1(76.43,16.79) 76.43,14.25 76.69,13.99 U32.M1 ; v1(70.12,16.61) 70.75,15.99 70.75,14.83 71.11,14.46 U32.E1 ; 72.42,15.78 72.42,14.29 U32.G1 ; U32.G9 v2(73.11,7.19) ; U17.4 v1(23.01,53.61) ; U21.2 v1(122.3,46.74) ; v1(68.02,6.93) 68.02,6.9 U32.B9 ; U32.E8 v2(70.71,8.8) ; U32.B1 68.68,13.99 67.82,14.86 v1(67.69,14.86) ; U32.A9 64.67,7.6 v1(64.34,7.92) ; U29.9 v1(56.22,21.08) ; U29.8 v1(56.22,24.28) ; U32.M9 76.08,6.96 v2(75.44,6.96) ; C254.2 87.31,25.85 R218.1 ; U32.T9 80.32,7.19 v2(80.32,6.98) ; v1(43.28,65.17) J3.5 ; U32.D8 v2(69.91,7.99) ; v1(95.17,32.92) 95.17,32.76 95.55,32.39 R207.1 ; v1(71.52,6.95) 71.51,6.95 71.51,7.19 U32.F9 ; U32.J8 v2(73.91,8.8) ; U32.P9 v2(77.91,7.2) ; U32.J2 v2(74.71,13.6)
  BOTTOM w0.508: R143.1 C214.2 v1(66.99,45.97) ; R245.2 v1(90.31,5.66) ; v1(95.34,11.37) 94.82,10.85 J12.16 ; C224.2 90.08,40.3 91.27,40.3 v1(91.57,40) ; J12.20 92.29,9.2 92.29,10.95 v1(92.16,11.08) ; R104.1 v1(120.52,55.12) ; v1(99.65,47.32) 100,46.97 C202.1 ; R166.1 v1(129.93,40.9) ; SW5.2 127.51,55.58 v1(127.51,53.97) ; v1(18.75,51) 17.86,50.11 U18.1 ; C212.2 v1(109.85,46.8) ; FB12.1 v1(117.03,69.4) ; FB12.1 v1(117.03,67) ; FB12.1 v1(118.24,68.2) ; C256.2 88.01,24.13 v1(88.57,24.69) ; v1(18.89,52.95) 18.97,53.02 C193.2 19.92,51.92 v1(20.02,51.82) ; R101.1 v1(37.56,57.91) ; R172.1 131.95,40.13 v1(131.7,40.39) ; v1(132.17,13.53) 131.41,14.29 SW7.2 ; C227.2 v1(121.88,37.21) ; C241.1 33.15,31.37 v1(32.72,31.37) ; C275.2 97.23,15.31 v1(97.66,15.75) ; v1(46.15,51.49) 45.97,51.31 C195.2 ; R146.1 100.56,43.69 v1(100.31,43.94) ; v1(66.1,48.33) 65.87,48.1 65.87,47.89 C203.2 ; v1(121.62,46.76) 121.64,46.74 v1(122.3,46.74) v1(122.96,46.74) ; v1(121.85,36.2) C232.2 ; v1(59.69,47.23) C204.2 v1(60.96,48.51) ; v1(120.05,39.57) C225.2 ; R236.1 v1(102.49,16.26) ; C242.2 49.11,32 48.55,32.56 v1(48.49,32.56) ; C209.1 54.1,45.97 54.41,46.28 v1(54.61,46.28) ; v1(103.08,36.37) 102.98,36.37 102.39,36.37 C229.2 ; C243.2 v1(132.08,32) ; C236.2 87.7,35.25 v1(88.01,35.56) ; C201.1 103.5,46.81 v1(104.22,46.81) ; v1(23.73,33.94) A1.22 ; C210.2 112.08,46.1 v1(111.9,45.92) ; J12.8 v1(99.9,11.01) ; v1(122.94,51.18) C197.2 v1(122.05,52.07) ; C231.2 33.1,36.91 v1(33.61,37.41) ; J12.12 v1(97.36,11.01) ; v1(113.41,46.86) 113.41,47.5 R125.1 ; v1(30.99,32.39) 29.79,33.58 U27.6 28.5,33.58 27.94,33.02 v1(27.94,32.39) ; v1(95,14.99) 94.76,15.23 C274.2 ; C206.2 85.72,47.3 85.38,47.65 v1(84.66,47.65) ; C263.2 v1(132.08,21.97) ; FB13.1 v1(50.25,65.04) ; FB13.1 v1(48.98,63.64) ; FB13.1 v1(47.58,65.04) ; R145.1 v1(59.56,44.2) ; v1(48.81,35.74) 48.48,36.07 C233.1 ; C196.1 v1(43.69,50.55) ; Q2.S v1(117.4,65.99) ; v1(32.21,25.1) 31.71,25.6 C252.2 ; R165.1 C220.2 v1(132.33,40.89) ; R231.1 v1(132.08,17.27) ; C272.2 41.71,17.27 42.09,16.89 v1(42.09,16.56) ; v1(90.68,32.77) R210.2 ; v1(50.8,39.79) C223.2 ; J12.10 v1(98.63,7.31) ; R99.2 45.97,60.89 v1(46.54,60.33) ; C240.2 R70.1 v1(101.47,31.67) ; C198.2 v1(21.55,52.24) ; v1(20.9,32.28) A1.20 ; J4.9 v1(108.55,57.24) ; R12.1 v1(37.56,55.63) ; C265.2 v1(43.05,19.34) ; SW7.1 v1(131.41,11.34) ; v1(29.42,25.6) 29.17,25.86 U27.3 v1(29.17,28.52) ; C238.2 115.53,32.03 v1(115.25,31.75) ; v1(88.14,25.27) 88.01,25.4 C254.2 ; v1(105.75,42.67) 104.86,42.67 C219.2 ; v1(50.29,19.3) 50.29,19.94 C264.2 ; v1(128.4,60.2) 128.27,60.33 127.51,60.33 127.29,60.55 SW5.1 ; v1(34.27,19.94) 34.54,19.67 C270.2 ; v1(87.7,32.52) 87.7,32.53 87.26,32.96 C239.2 ; C194.1 v1(46.99,52.2) ; v1(58.07,46.01) 58.05,46.01 57.77,45.72 C208.1 ; R226.1 76.46,20.83 76.53,20.9 v1(76.92,20.9) ; R14.1 v1(37.56,53.34) ; C217.2 v1(123.83,43.94) ; C211.2 v1(111,46.8) ; R98.1 v1(113.54,64.01) ; C140.2 v1(88.69,18.03) ; C259.2 v1(49.66,24) ; v1(93.53,31.62) R209.1 ; C276.2 33.48,15.62 v1(33.38,15.52) ; C199.2 49.46,47.69 v1(49.47,47.69) ; v1(49.92,27.36) 49.89,27.38 49.45,27.38 C248.2 ; C190.2 v1(21.67,53.45) ; C205.2 87.31,44.79 C216.2 87.52,44.46 85.3,42.24 v1(85.25,42.24) ; C246.2 v1(32.72,30.61) ; R127.2 v1(14.05,45.34) ; 58.86,24 C258.2 v1(58.1,24) ; v1(53.84,31.88) 53.4,32.25 R198.1 R199.1 ; C251.1 v1(32.82,25.98) ; R100.1 v1(113.54,60.2) ; C191.2 v1(110.11,54.61) ; C207.2 v1(21.42,45.42) ; C218.2 v1(61.65,43.1) ; C266.2 v1(36.83,20.07) ; Q5.S v1(118.54,57.86) ; Q4.S v1(123.62,57.86) ; R119.1 v1(41.46,50.55) ; C188.2 v1(38.06,64.34) ; C279.2 v1(125.22,7.75) ; C221.2 v1(107.24,42.72) ; C230.2 v1(14.81,35.64) ; R214.1 v1(49.79,29.84) ; R53.1 v1(103.08,37.47) ; R193.1 C237.2 59.49,32.15 v1(59.18,31.84) ; Q3.S v1(117.4,62.18) ; R105.1 v1(116.28,55.88) ; R215.1 v1(132.08,27.3) ; v1(132.33,35.69) 131.95,36.07 C228.2 ; C213.2 v1(108.71,46.8) ; R235.2 v1(104.77,17.14) ; C200.2 v1(44.83,47.5) ; C253.1 v1(50.51,25.02) ; C192.2 v1(114.3,55.37) ; C222.2 v1(103.94,41.58)
  BOTTOM w0.635: R242.1 v1(85.36,5.75)
  BOTTOM w1.016: MH3.1 12.35,8.06 ; MH3.1 12.35,12.15 ; MH3.1 8.26,8.06 ; MH3.1 8.26,12.15
  vias: v1(3.71,30.92) v1(3.71,29.92) v1(3.71,28.92) v1(3.71,27.92) v1(3.71,26.92) v1(3.71,25.92) v1(3.71,24.92) v1(3.71,23.92) v1(3.71,22.92) v1(3.71,21.92) v1(3.71,20.92) v1(4.71,30.92) v1(4.71,29.92) v1(4.71,28.92) v1(4.71,27.92) v1(4.71,26.92) v1(4.71,25.92) v1(4.71,24.92) v1(4.71,23.92) v1(4.71,22.92) v1(4.71,21.92) v1(4.71,20.92) v1(5.71,30.92) v1(5.71,29.92) v1(5.71,28.92) v1(5.71,27.92) v1(5.71,26.92) v1(5.71,25.92) v1(5.71,24.92) v1(5.71,23.92) v1(5.71,22.92) v1(5.71,21.92) v1(5.71,20.92) v1(5.71,19.92) v1(5.71,18.92) v1(5.71,17.92) v1(5.71,16.92) v1(5.71,15.92) v1(5.71,14.92) v1(5.71,13.34) v1(5.71,12.34) v1(5.71,11.34) v1(5.71,10.34) v1(5.71,9.21) v1(5.71,8.16) v1(6.71,30.92) v1(6.71,29.92) v1(6.71,28.92) v1(6.71,27.92) v1(6.71,26.92) v1(6.71,25.92) v1(6.71,24.92) v1(6.71,23.92) v1(6.71,22.92) v1(6.71,21.92) v1(6.71,20.92) v1(6.71,19.92) v1(6.71,18.92) v1(6.71,17.92) v1(6.71,16.92) v1(6.71,15.92) v1(6.71,14.92) v1(6.71,13.34) v1(6.71,12.34) v1(6.71,11.34) v1(6.71,9.21) v1(6.71,8.16) v1(6.84,7.04) v1(7.71,30.92) v1(7.71,29.92) v1(7.71,28.92) v1(7.71,27.92) v1(7.71,26.92) v1(7.71,25.92) v1(7.71,24.92) v1(7.71,23.92) v1(7.71,22.92) v1(7.71,21.92) v1(7.71,20.92) v1(7.71,19.92) v1(7.71,18.92) v1(7.71,17.92) v1(7.71,16.92) v1(7.71,15.92) v1(7.71,14.92) v1(7.71,13.23) v1(7.84,7.04) v1(8.71,30.92) v1(8.71,29.92) v1(8.71,28.92) v1(8.71,27.92) v1(8.71,26.92) v1(8.71,25.92) v1(8.71,24.92) v1(8.71,23.92) v1(8.71,22.92) v1(8.71,21.92) v1(8.71,20.92) v1(8.71,19.92) v1(8.71,18.92) v1(8.71,17.92) v1(8.71,16.92) v1(8.71,15.92) v1(8.71,14.92) v1(9.71,30.92) v1(9.71,29.92) v1(9.71,28.92) v1(9.71,27.92) v1(9.71,26.92) v1(9.71,25.92) v1(9.71,24.92) v1(9.71,23.92) v1(9.71,22.92) v1(9.71,21.92) v1(9.71,20.92) v1(9.71,19.92) v1(9.71,18.92) v1(9.71,17.92) v1(9.71,16.92) v1(9.71,15.92) v1(9.71,14.92) v1(10.71,30.92) v1(10.71,29.92) v1(10.71,28.92) v1(10.71,27.92) v1(10.71,26.92) v1(10.71,25.92) v1(10.71,24.92) v1(10.71,23.92) v1(10.71,22.92) v1(10.71,21.92) v1(10.71,20.92) v1(10.71,19.92) v1(10.71,18.92) v1(10.71,17.92) v1(10.71,16.92) v1(10.71,15.92) v1(11.71,30.92) v1(11.71,29.92) v1(11.71,28.92) v1(11.71,27.92) v1(11.71,26.92) v1(11.71,25.92) v1(11.71,24.92) v1(11.71,23.92) v1(11.71,22.92) v1(11.71,21.92) v1(11.71,20.92) v1(11.71,19.92) v1(11.71,18.92) v1(11.71,17.92) v1(11.71,16.92) v1(11.71,15.92) v1(11.71,14.92) v1(12.65,25.93) v1(12.62,21.87) v1(12.65,20.9) v1(12.71,30.92) v1(12.71,29.92) v1(12.71,27.92) v1(12.71,26.92) v1(12.71,24.92) v1(12.71,23.92) v1(12.71,22.92) v1(12.71,19.92) v1(12.71,18.92) v1(12.71,17.92) v1(12.71,16.92) v1(12.71,15.92) v1(12.71,14.92) v1(12.71,13.27) v1(12.98,6.92) v1(13.37,23.09) v1(13.71,18.92) v1(13.71,17.92) v1(13.71,16.92) v1(13.71,15.92) v1(13.71,14.92) v1(13.71,13.27) v1(13.98,11.92) v1(13.98,10.92) v1(13.98,9.92) v1(13.98,8.92) v1(13.98,7.92) v1(13.98,6.92) v1(14.71,16.92) v1(14.71,15.92) v1(14.98,11.92) v1(14.98,10.92) v1(14.98,9.92) v1(14.98,8.92) v1(14.98,7.92) v1(14.98,6.92) v1(15.7,45.8) v1(15.66,32.09) v1(15.73,20.95) v1(15.73,20.09) v1(15.71,16.92) v1(15.71,15.92) v1(15.7,15.02) v1(15.7,14.02) v1(15.7,13.02) v1(15.88,31.37) v1(15.88,29.21) v1(15.88,27.69) v1(15.88,26.04) v1(15.88,22.86) v1(15.98,11.92) v1(15.98,10.92) v1(15.98,9.92) v1(15.98,8.92) v1(15.98,7.92) v1(15.98,6.92) v1(16.43,30.09) v1(16.43,28.49) v1(16.43,26.89) v1(16.43,25.29) v1(16.43,23.69) v1(16.43,22.09) v1(16.47,45.8) v1(16.71,16.92) v1(16.71,15.92) v1(16.8,20.95) v1(16.8,20.09) v1(17.02,31.37) v1(17.02,29.21) v1(17.02,27.69) v1(17.02,26.04) v1(17.02,24.51) v1(17.02,22.86) v1(16.98,11.92) v1(16.98,10.92) v1(16.98,9.92) v1(16.98,8.92) v1(16.98,7.92) v1(16.98,6.92) v1(17.71,16.92) v1(17.71,15.92) v1(17.71,14.92) v1(17.9,20.95) v1(17.9,20.09) v1(17.9,19.42) v1(17.98,12.92) v1(17.98,11.92) v1(17.98,10.92) v1(17.98,9.92) v1(17.98,8.92) v1(17.98,7.92) v1(17.98,6.92) v1(18.11,45.92) v1(18.29,31.37) v1(18.41,29.21) v1(18.41,27.69) v1(18.41,26.04) v1(18.41,24.51) v1(18.41,22.86) v1(18.9,30.89) v1(18.9,20.95) v1(18.9,20.09) v1(18.98,12.92) v1(18.98,11.92) v1(18.98,10.92) v1(18.98,9.92) v1(18.98,8.92) v1(18.98,7.92) v1(18.98,6.92) v1(19.64,24.59) v1(19.64,22.81) v1(19.67,31.39) v1(19.67,29.24) v1(19.68,27.69) v1(19.67,26.06) v1(19.89,20.95) v1(19.89,20.09) v1(19.9,19.42) v1(19.94,17.02) v1(19.98,15.92) v1(19.98,14.92) v1(19.98,13.92) v1(19.98,12.92) v1(19.98,11.92) v1(19.98,10.92) v1(19.98,9.92) v1(19.98,8.92) v1(19.98,7.92) v1(19.98,6.92) v1(20.7,29.21) v1(20.7,27.69) v1(20.7,26.04) v1(20.83,31.37) v1(20.83,22.86) v1(20.9,17.06) v1(20.96,20.95) v1(20.96,20.09) v1(20.98,15.92) v1(20.98,14.92) v1(20.98,13.92) v1(20.98,12.92) v1(20.98,11.92) v1(20.98,10.92) v1(20.98,9.92) v1(20.98,8.92) v1(20.98,7.92) v1(20.98,6.92) v1(21.59,26.16) v1(21.72,29.21) v1(21.72,27.69) v1(21.9,17.06) v1(22.03,20.95) v1(21.98,15.92) v1(21.98,14.92) v1(21.98,13.92) v1(21.98,12.92) v1(21.98,11.92) v1(21.98,10.92) v1(21.98,9.92) v1(21.98,8.92) v1(21.98,7.92) v1(21.98,6.92) v1(22.08,24.03) v1(22.07,20.09) v1(22.43,51.62) v1(22.9,17.06) v1(22.98,15.92) v1(22.98,14.92) v1(22.98,13.92) v1(22.98,12.92) v1(22.98,11.92) v1(22.98,10.92) v1(22.98,9.92) v1(22.98,8.92) v1(22.98,7.92) v1(22.98,6.92) v1(23.9,17.06) v1(23.96,19.38) v1(23.96,18.36) v1(23.98,15.92) v1(23.98,14.92) v1(23.98,13.92) v1(23.98,12.92) v1(23.98,11.92) v1(23.98,10.92) v1(23.98,9.92) v1(23.98,8.92) v1(23.98,7.92) v1(23.98,6.92) v1(24.42,34.75) v1(24.42,33.68) v1(25.1,51.62) v1(25.65,25.91) v1(27.05,15.11) v1(27.05,14.35) v1(27.3,43.94) v1(27.81,15.11) v1(27.81,14.35) v1(28.07,43.94) v1(28.61,40.72) v1(28.83,43.94) v1(28.83,43.18) v1(28.83,42.42) v1(31.75,35.57) v1(32.38,35.56) v1(35.49,12.68) v1(42.67,57.91) v1(42.67,55.63) v1(43.82,57.91) v1(43.82,56.79) v1(44.96,56.77) v1(50.98,62.99) v1(54.79,38.48) v1(55.73,39.65) v1(57.91,23.04) v1(58.55,18.47) v1(60.83,22.99) v1(62.69,20.6) v1(63.7,18.16) v1(64.26,16.38) v1(72.4,16.76) v1(79.21,1.72) v1(79.9,1.72) v1(79.99,44.37) v1(80.64,1.65) v1(81.41,1.65) v1(88.03,1.78) v1(88.9,43.31) v1(88.98,6.6) v1(90.35,19.69) v1(90.56,1.8) v1(90.93,42.67) v1(90.99,20.35) v1(94.74,39.75) v1(94.74,38.48) v1(95.35,20.98) v1(96.01,39.75) v1(96.01,20.96) v1(96.65,20.96) v1(98.37,23.24) v1(102.11,20.07) v1(102.06,19.38) v1(102.06,18.49) v1(103.12,20.07) v1(103.08,19.38) v1(103.08,18.49) v1(104.14,20.07) v1(104.1,19.38) v1(104.1,18.49) v1(105.16,18.54) v1(107.25,58.88) v1(108.42,2.76) v1(108.49,60.01) v1(110.83,47.83) v1(111.05,49.78) v1(111.9,46.81) v1(112.62,40.49) v1(113.08,39.07) v1(113.4,2.89) v1(114.1,39.93) v1(114.57,28.27) v1(114.87,40.88) v1(115.33,29.03) v1(115.33,28.27) v1(115.95,44.32) v1(116.09,29.03) v1(116.09,28.27) v1(116.85,29.03) v1(119.89,23.24) v1(119.89,22.23) v1(119.89,21.21) v1(121.16,25.12) v1(122.05,25.12) v1(122.3,15.75) v1(123.32,21.72) v1(123.27,15.75) v1(124.08,15.47) v1(124.1,14.73) v1(124.1,13.97) v1(128.51,37.54) v1(128.54,36.77) v1(130.01,37.49) v1(130.01,36.7) v1(130.01,35.81) v1(130.04,34.97) v2(76.74,30.61) v2(81.71,27.69) v2(82.22,27.25)
